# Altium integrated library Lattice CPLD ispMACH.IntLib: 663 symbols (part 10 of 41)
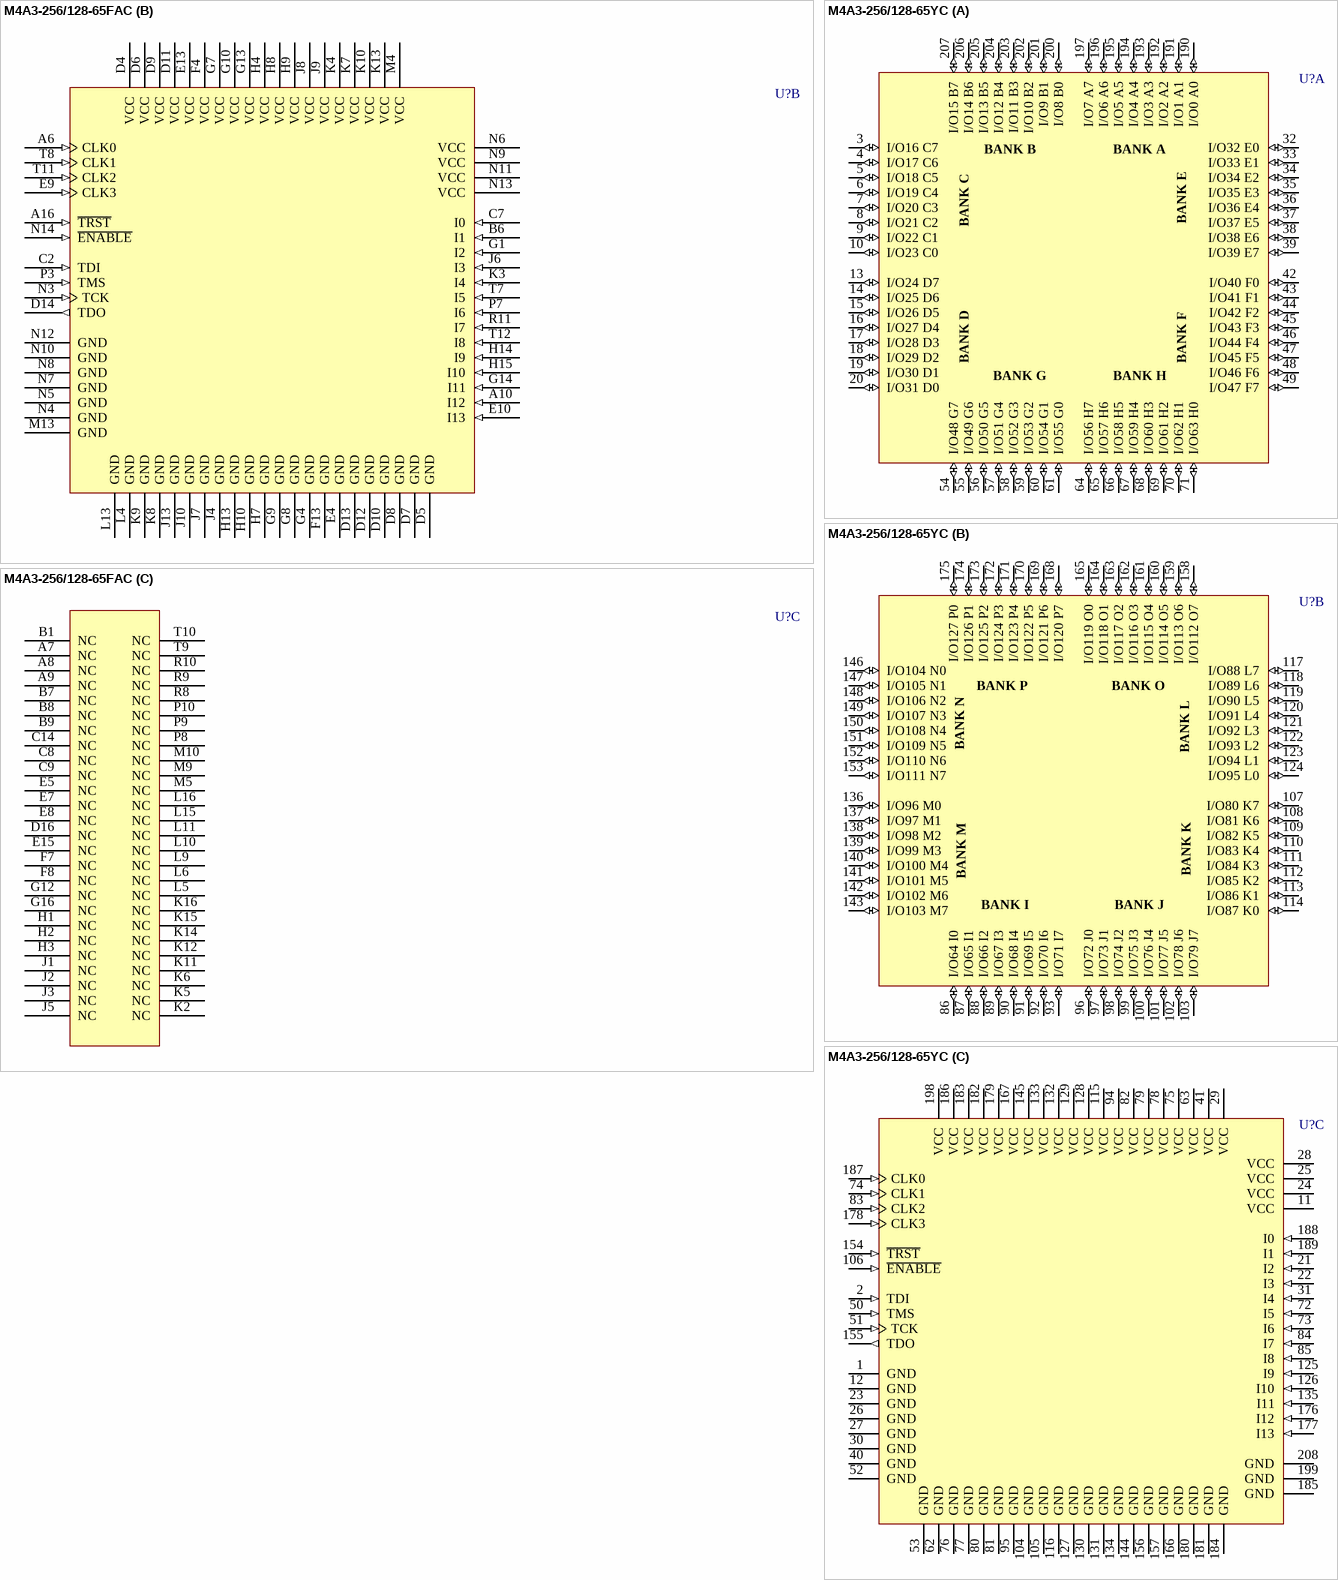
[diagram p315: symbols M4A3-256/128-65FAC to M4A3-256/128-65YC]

## M4A3-256/128-65YC
designator U?
High-Performance EE CMOS In-System Programmable Logic
footprint PQFP208_N (Shrink QFP, 208-Leads, Body 28x28mm, Pitch 0.5mm, IPC Medium Density)
footprint PQFP208_L (Shrink QFP, 208-Leads, Body 28x28mm, Pitch 0.5mm, IPC High Density)
footprint PQFP208_M (Shrink QFP, 208-Leads, Body 28x28mm, Pitch 0.5mm, IPC Low Density)
3D model M4A3-PQFP208 (208-Pin Plastic Quad Flat Pack (PQFP208))
part A pins: 3 I/O16 C7 (io), 4 I/O17 C6 (io), 5 I/O18 C5 (io), 6 I/O19 C4 (io), 7 I/O20 C3 (io), 8 I/O21 C2 (io), 9 I/O22 C1 (io), 10 I/O23 C0 (io), 13 I/O24 D7 (io), 14 I/O25 D6 (io), 15 I/O26 D5 (io), 16 I/O27 D4 (io), 17 I/O28 D3 (io), 18 I/O29 D2 (io), 19 I/O30 D1 (io), 20 I/O31 D0 (io), 32 I/O32 E0 (io), 33 I/O33 E1 (io), 34 I/O34 E2 (io), 35 I/O35 E3 (io), 36 I/O36 E4 (io), 37 I/O37 E5 (io), 38 I/O38 E6 (io), 39 I/O39 E7 (io), 42 I/O40 F0 (io), 43 I/O41 F1 (io), 44 I/O42 F2 (io), 45 I/O43 F3 (io), 46 I/O44 F4 (io), 47 I/O45 F5 (io), 48 I/O46 F6 (io), 49 I/O47 F7 (io), 54 I/O48 G7 (io), 55 I/O49 G6 (io), 56 I/O50 G5 (io), 57 I/O51 G4 (io), 58 I/O52 G3 (io), 59 I/O53 G2 (io), 60 I/O54 G1 (io), 61 I/O55 G0 (io), 64 I/O56 H7 (io), 65 I/O57 H6 (io), 66 I/O58 H5 (io), 67 I/O59 H4 (io), 68 I/O60 H3 (io), 69 I/O61 H2 (io), 70 I/O62 H1 (io), 71 I/O63 H0 (io), 190 I/O0 A0 (io), 191 I/O1 A1 (io), 192 I/O2 A2 (io), 193 I/O3 A3 (io), 194 I/O4 A4 (io), 195 I/O5 A5 (io), 196 I/O6 A6 (io), 197 I/O7 A7 (io), 200 I/O8 B0 (io), 201 I/O9 B1 (io), 202 I/O10 B2 (io), 203 I/O11 B3 (io), 204 I/O12 B4 (io), 205 I/O13 B5 (io), 206 I/O14 B6 (io), 207 I/O15 B7 (io)
part B pins: 86 I/O64 I0 (io), 87 I/O65 I1 (io), 88 I/O66 I2 (io), 89 I/O67 I3 (io), 90 I/O68 I4 (io), 91 I/O69 I5 (io), 92 I/O70 I6 (io), 93 I/O71 I7 (io), 96 I/O72 J0 (io), 97 I/O73 J1 (io), 98 I/O74 J2 (io), 99 I/O75 J3 (io), 100 I/O76 J4 (io), 101 I/O77 J5 (io), 102 I/O78 J6 (io), 103 I/O79 J7 (io), 107 I/O80 K7 (io), 108 I/O81 K6 (io), 109 I/O82 K5 (io), 110 I/O83 K4 (io), 111 I/O84 K3 (io), 112 I/O85 K2 (io), 113 I/O86 K1 (io), 114 I/O87 K0 (io), 117 I/O88 L7 (io), 118 I/O89 L6 (io), 119 I/O90 L5 (io), 120 I/O91 L4 (io), 121 I/O92 L3 (io), 122 I/O93 L2 (io), 123 I/O94 L1 (io), 124 I/O95 L0 (io), 136 I/O96 M0 (io), 137 I/O97 M1 (io), 138 I/O98 M2 (io), 139 I/O99 M3 (io), 140 I/O100 M4 (io), 141 I/O101 M5 (io), 142 I/O102 M6 (io), 143 I/O103 M7 (io), 146 I/O104 N0 (io), 147 I/O105 N1 (io), 148 I/O106 N2 (io), 149 I/O107 N3 (io), 150 I/O108 N4 (io), 151 I/O109 N5 (io), 152 I/O110 N6 (io), 153 I/O111 N7 (io), 158 I/O112 O7 (io), 159 I/O113 O6 (io), 160 I/O114 O5 (io), 161 I/O115 O4 (io), 162 I/O116 O3 (io), 163 I/O117 O2 (io), 164 I/O118 O1 (io), 165 I/O119 O0 (io), 168 I/O120 P7 (io), 169 I/O121 P6 (io), 170 I/O122 P5 (io), 171 I/O123 P4 (io), 172 I/O124 P3 (io), 173 I/O125 P2 (io), 174 I/O126 P1 (io), 175 I/O127 P0 (io)
part C pins: 1 GND (power), 2 TDI (in), 11 VCC (power), 12 GND (power), 21 I2 (in), 22 I3 (in), 23 GND (power), 24 VCC (power), 25 VCC (power), 26 GND (power), 27 GND (power), 28 VCC (power), 29 VCC (power), 30 GND (power), 31 I4 (in), 40 GND (power), 41 VCC (power), 50 TMS (in), 51 TCK (in), 52 GND (power), 53 GND (power), 62 GND (power), 63 VCC (power), 72 I5 (in), 73 I6 (in), 74 CLK1 (in), 75 VCC (power), 76 GND (power), 77 GND (power), 78 VCC (power), 79 VCC (power), 80 GND (power), 81 GND (power), 82 VCC (power), 83 CLK2 (in), 84 I7 (in), 85 I8 (in), 94 VCC (power), 95 GND (power), 104 GND (power), 105 GND (power), 106 ~{ENABLE} (in), 115 VCC (power), 116 GND (power), 125 I9 (in), 126 I10 (in), 127 GND (power), 128 VCC (power), 129 VCC (power), 130 GND (power), 131 GND (power), 132 VCC (power), 133 VCC (power), 134 GND (power), 135 I11 (in), 144 GND (power), 145 VCC (power), 154 ~{TRST} (in), 155 TDO (out), 156 GND (power), 157 GND (power), 166 GND (power), 167 VCC (power), 176 I12 (in), 177 I13 (in), 178 CLK3 (in), 179 VCC (power), 180 GND (power), 181 GND (power), 182 VCC (power), 183 VCC (power), 184 GND (power), 185 GND (power), 186 VCC (power), 187 CLK0 (in), 188 I0 (in), 189 I1 (in), 198 VCC (power), 199 GND (power), 208 GND (power)

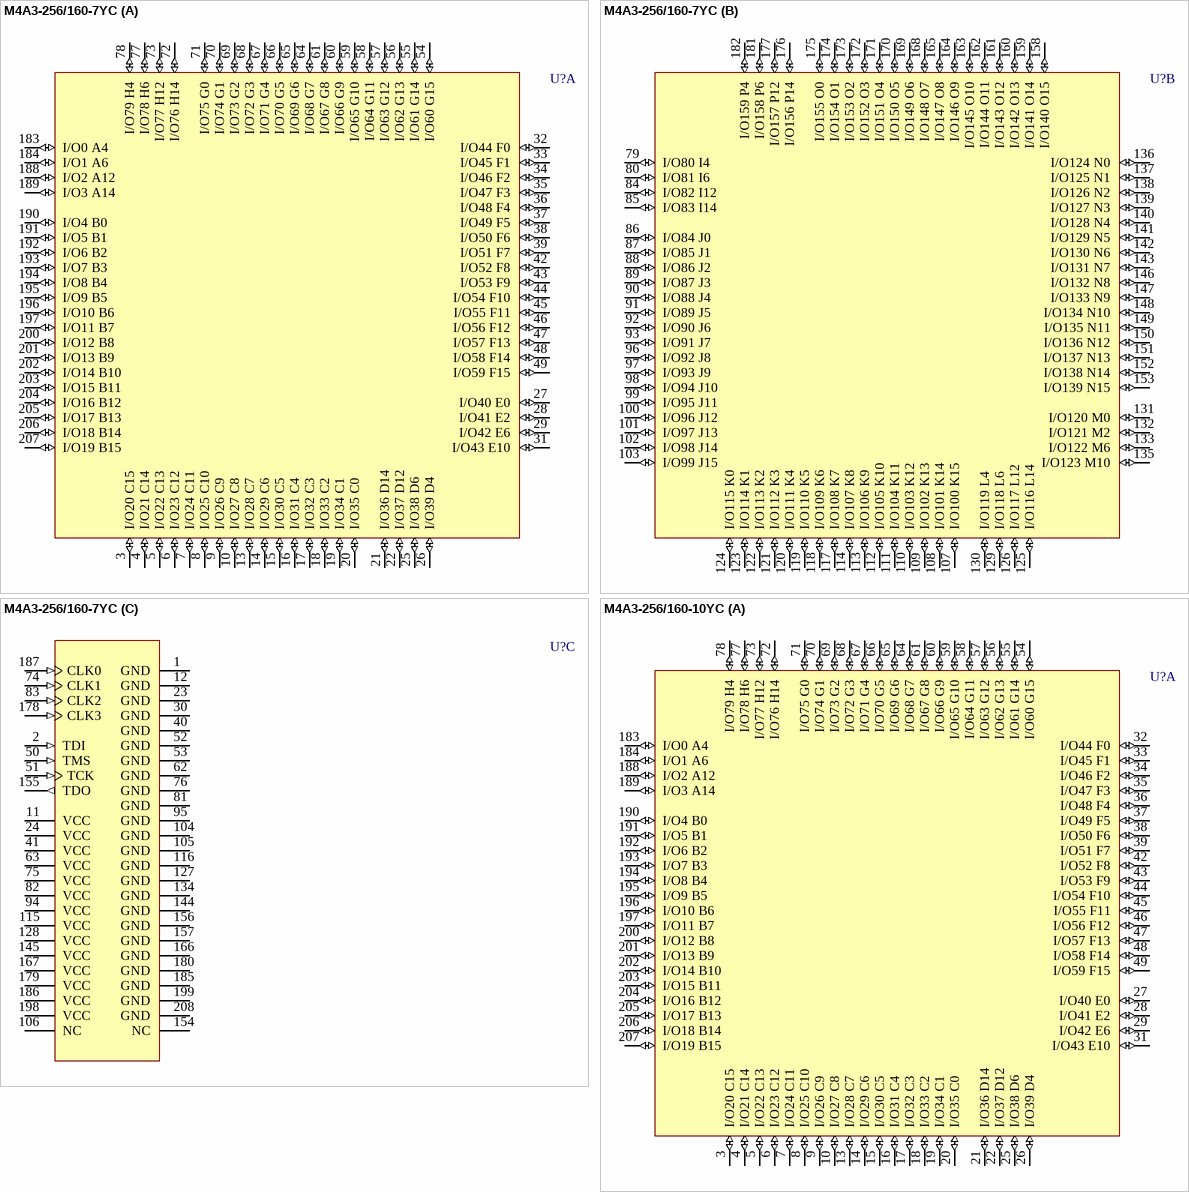
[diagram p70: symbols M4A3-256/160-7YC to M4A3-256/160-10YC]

## M4A3-256/160-7YC
designator U?
High-Performance EE CMOS In-System Programmable Logic
footprint PQFP208_N (Shrink QFP, 208-Leads, Body 28x28mm, Pitch 0.5mm, IPC Medium Density)
footprint PQFP208_L (Shrink QFP, 208-Leads, Body 28x28mm, Pitch 0.5mm, IPC High Density)
footprint PQFP208_M (Shrink QFP, 208-Leads, Body 28x28mm, Pitch 0.5mm, IPC Low Density)
3D model M4A3-PQFP208 (208-Pin Plastic Quad Flat Pack (PQFP208))
part A pins: 3 I/O20 C15 (io), 4 I/O21 C14 (io), 5 I/O22 C13 (io), 6 I/O23 C12 (io), 7 I/O24 C11 (io), 8 I/O25 C10 (io), 9 I/O26 C9 (io), 10 I/O27 C8 (io), 13 I/O28 C7 (io), 14 I/O29 C6 (io), 15 I/O30 C5 (io), 16 I/O31 C4 (io), 17 I/O32 C3 (io), 18 I/O33 C2 (io), 19 I/O34 C1 (io), 20 I/O35 C0 (io), 21 I/O36 D14 (io), 22 I/O37 D12 (io), 25 I/O38 D6 (io), 26 I/O39 D4 (io), 27 I/O40 E0 (io), 28 I/O41 E2 (io), 29 I/O42 E6 (io), 31 I/O43 E10 (io), 32 I/O44 F0 (io), 33 I/O45 F1 (io), 34 I/O46 F2 (io), 35 I/O47 F3 (io), 36 I/O48 F4 (io), 37 I/O49 F5 (io), 38 I/O50 F6 (io), 39 I/O51 F7 (io), 42 I/O52 F8 (io), 43 I/O53 F9 (io), 44 I/O54 F10 (io), 45 I/O55 F11 (io), 46 I/O56 F12 (io), 47 I/O57 F13 (io), 48 I/O58 F14 (io), 49 I/O59 F15 (io), 54 I/O60 G15 (io), 55 I/O61 G14 (io), 56 I/O62 G13 (io), 57 I/O63 G12 (io), 58 I/O64 G11 (io), 59 I/O65 G10 (io), 60 I/O66 G9 (io), 61 I/O67 G8 (io), 64 I/O68 G7 (io), 65 I/O69 G6 (io), 66 I/O70 G5 (io), 67 I/O71 G4 (io), 68 I/O72 G3 (io), 69 I/O73 G2 (io), 70 I/O74 G1 (io), 71 I/O75 G0 (io), 72 I/O76 H14 (io), 73 I/O77 H12 (io), 77 I/O78 H6 (io), 78 I/O79 H4 (io), 183 I/O0 A4 (io), 184 I/O1 A6 (io), 188 I/O2 A12 (io), 189 I/O3 A14 (io), 190 I/O4 B0 (io), 191 I/O5 B1 (io), 192 I/O6 B2 (io), 193 I/O7 B3 (io), 194 I/O8 B4 (io), 195 I/O9 B5 (io), 196 I/O10 B6 (io), 197 I/O11 B7 (io), 200 I/O12 B8 (io), 201 I/O13 B9 (io), 202 I/O14 B10 (io), 203 I/O15 B11 (io), 204 I/O16 B12 (io), 205 I/O17 B13 (io), 206 I/O18 B14 (io), 207 I/O19 B15 (io)
part B pins: 79 I/O80 I4 (io), 80 I/O81 I6 (io), 84 I/O82 I12 (io), 85 I/O83 I14 (io), 86 I/O84 J0 (io), 87 I/O85 J1 (io), 88 I/O86 J2 (io), 89 I/O87 J3 (io), 90 I/O88 J4 (io), 91 I/O89 J5 (io), 92 I/O90 J6 (io), 93 I/O91 J7 (io), 96 I/O92 J8 (io), 97 I/O93 J9 (io), 98 I/O94 J10 (io), 99 I/O95 J11 (io), 100 I/O96 J12 (io), 101 I/O97 J13 (io), 102 I/O98 J14 (io), 103 I/O99 J15 (io), 107 I/O100 K15 (io), 108 I/O101 K14 (io), 109 I/O102 K13 (io), 110 I/O103 K12 (io), 111 I/O104 K11 (io), 112 I/O105 K10 (io), 113 I/O106 K9 (io), 114 I/O107 K8 (io), 117 I/O108 K7 (io), 118 I/O109 K6 (io), 119 I/O110 K5 (io), 120 I/O111 K4 (io), 121 I/O112 K3 (io), 122 I/O113 K2 (io), 123 I/O114 K1 (io), 124 I/O115 K0 (io), 125 I/O116 L14 (io), 126 I/O117 L12 (io), 129 I/O118 L6 (io), 130 I/O119 L4 (io), 131 I/O120 M0 (io), 132 I/O121 M2 (io), 133 I/O122 M6 (io), 135 I/O123 M10 (io), 136 I/O124 N0 (io), 137 I/O125 N1 (io), 138 I/O126 N2 (io), 139 I/O127 N3 (io), 140 I/O128 N4 (io), 141 I/O129 N5 (io), 142 I/O130 N6 (io), 143 I/O131 N7 (io), 146 I/O132 N8 (io), 147 I/O133 N9 (io), 148 I/O134 N10 (io), 149 I/O135 N11 (io), 150 I/O136 N12 (io), 151 I/O137 N13 (io), 152 I/O138 N14 (io), 153 I/O139 N15 (io), 158 I/O140 O15 (io), 159 I/O141 O14 (io), 160 I/O142 O13 (io), 161 I/O143 O12 (io), 162 I/O144 O11 (io), 163 I/O145 O10 (io), 164 I/O146 O9 (io), 165 I/O147 O8 (io), 168 I/O148 O7 (io), 169 I/O149 O6 (io), 170 I/O150 O5 (io), 171 I/O151 O4 (io), 172 I/O152 O3 (io), 173 I/O153 O2 (io), 174 I/O154 O1 (io), 175 I/O155 O0 (io), 176 I/O156 P14 (io), 177 I/O157 P12 (io), 181 I/O158 P6 (io), 182 I/O159 P4 (io)
part C pins: 1 GND (power), 2 TDI (in), 11 VCC (power), 12 GND (power), 23 GND (power), 24 VCC (power), 30 GND (power), 40 GND (power), 41 VCC (power), 50 TMS (in), 51 TCK (in), 52 GND (power), 53 GND (power), 62 GND (power), 63 VCC (power), 74 CLK1 (in), 75 VCC (power), 76 GND (power), 81 GND (power), 82 VCC (power), 83 CLK2 (in), 94 VCC (power), 95 GND (power), 104 GND (power), 105 GND (power), 106 NC, 115 VCC (power), 116 GND (power), 127 GND (power), 128 VCC (power), 134 GND (power), 144 GND (power), 145 VCC (power), 154 NC, 155 TDO (out), 156 GND (power), 157 GND (power), 166 GND (power), 167 VCC (power), 178 CLK3 (in), 179 VCC (power), 180 GND (power), 185 GND (power), 186 VCC (power), 187 CLK0 (in), 198 VCC (power), 199 GND (power), 208 GND (power)

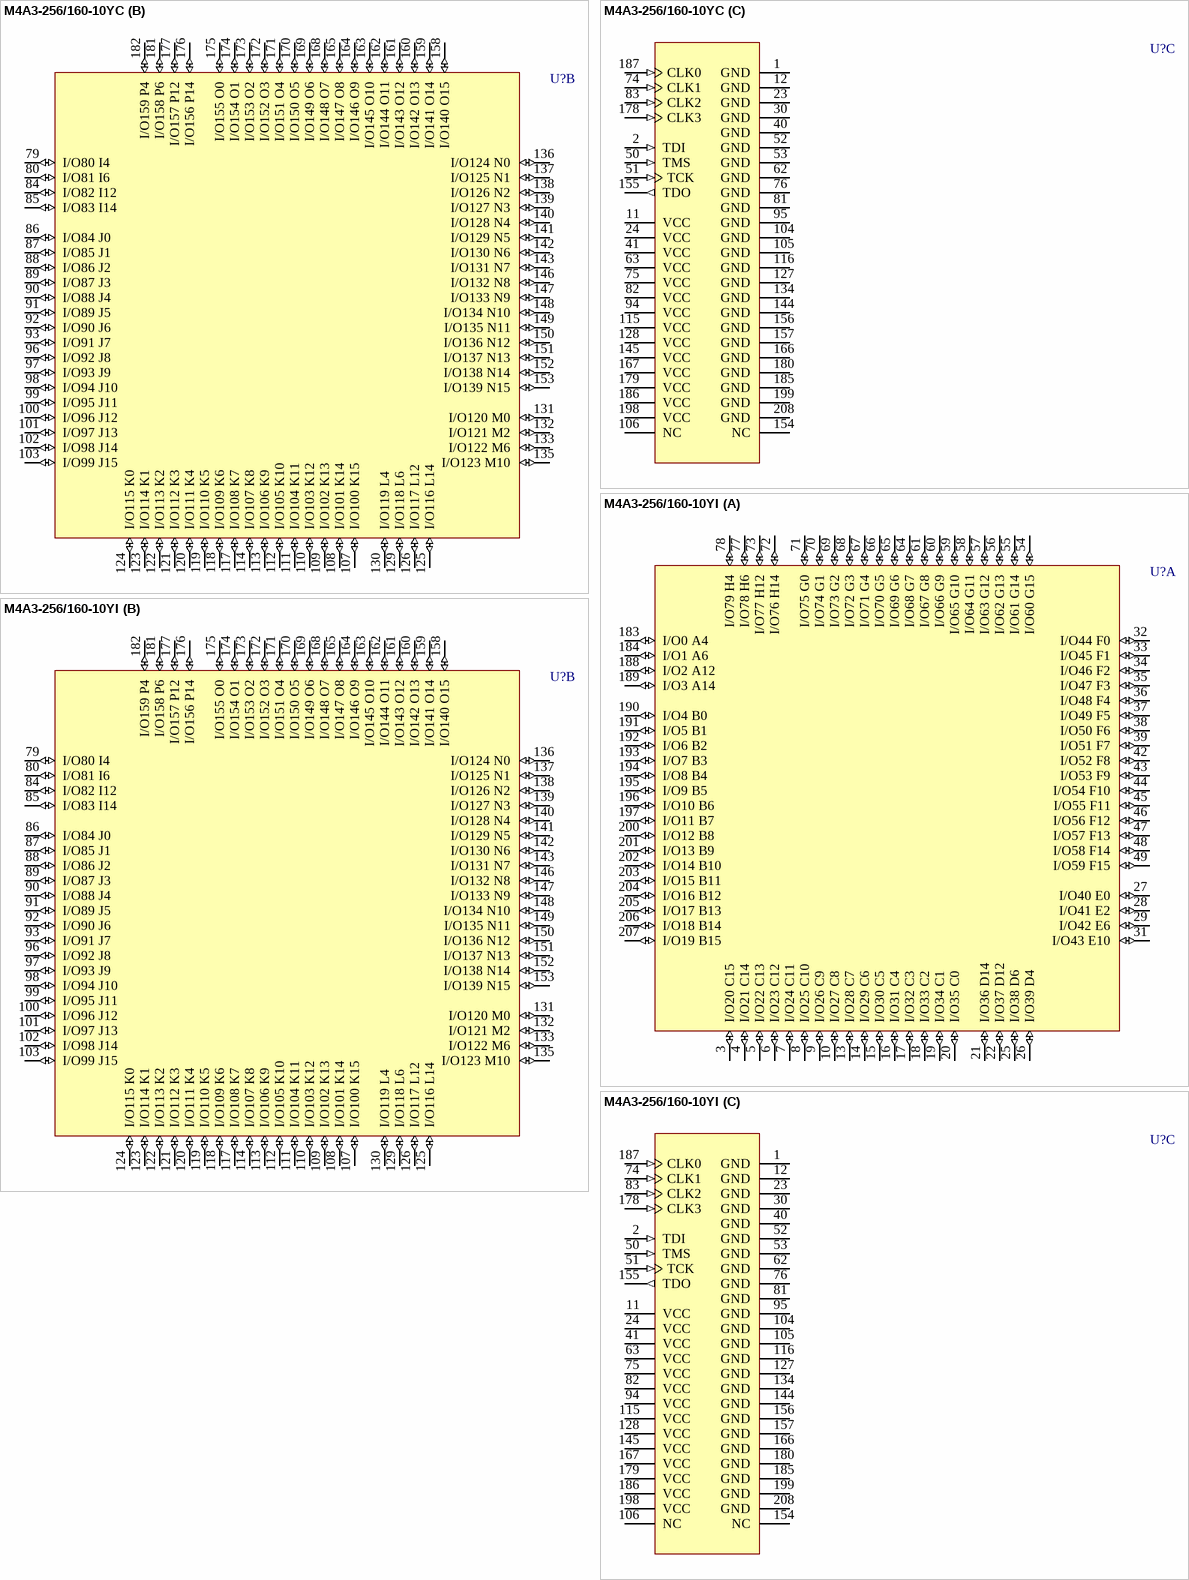
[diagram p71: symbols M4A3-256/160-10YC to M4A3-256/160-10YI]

## M4A3-256/160-10YC
designator U?
High-Performance EE CMOS In-System Programmable Logic
footprint PQFP208_N (Shrink QFP, 208-Leads, Body 28x28mm, Pitch 0.5mm, IPC Medium Density)
footprint PQFP208_L (Shrink QFP, 208-Leads, Body 28x28mm, Pitch 0.5mm, IPC High Density)
footprint PQFP208_M (Shrink QFP, 208-Leads, Body 28x28mm, Pitch 0.5mm, IPC Low Density)
3D model M4A3-PQFP208 (208-Pin Plastic Quad Flat Pack (PQFP208))
part A pins: 3 I/O20 C15 (io), 4 I/O21 C14 (io), 5 I/O22 C13 (io), 6 I/O23 C12 (io), 7 I/O24 C11 (io), 8 I/O25 C10 (io), 9 I/O26 C9 (io), 10 I/O27 C8 (io), 13 I/O28 C7 (io), 14 I/O29 C6 (io), 15 I/O30 C5 (io), 16 I/O31 C4 (io), 17 I/O32 C3 (io), 18 I/O33 C2 (io), 19 I/O34 C1 (io), 20 I/O35 C0 (io), 21 I/O36 D14 (io), 22 I/O37 D12 (io), 25 I/O38 D6 (io), 26 I/O39 D4 (io), 27 I/O40 E0 (io), 28 I/O41 E2 (io), 29 I/O42 E6 (io), 31 I/O43 E10 (io), 32 I/O44 F0 (io), 33 I/O45 F1 (io), 34 I/O46 F2 (io), 35 I/O47 F3 (io), 36 I/O48 F4 (io), 37 I/O49 F5 (io), 38 I/O50 F6 (io), 39 I/O51 F7 (io), 42 I/O52 F8 (io), 43 I/O53 F9 (io), 44 I/O54 F10 (io), 45 I/O55 F11 (io), 46 I/O56 F12 (io), 47 I/O57 F13 (io), 48 I/O58 F14 (io), 49 I/O59 F15 (io), 54 I/O60 G15 (io), 55 I/O61 G14 (io), 56 I/O62 G13 (io), 57 I/O63 G12 (io), 58 I/O64 G11 (io), 59 I/O65 G10 (io), 60 I/O66 G9 (io), 61 I/O67 G8 (io), 64 I/O68 G7 (io), 65 I/O69 G6 (io), 66 I/O70 G5 (io), 67 I/O71 G4 (io), 68 I/O72 G3 (io), 69 I/O73 G2 (io), 70 I/O74 G1 (io), 71 I/O75 G0 (io), 72 I/O76 H14 (io), 73 I/O77 H12 (io), 77 I/O78 H6 (io), 78 I/O79 H4 (io), 183 I/O0 A4 (io), 184 I/O1 A6 (io), 188 I/O2 A12 (io), 189 I/O3 A14 (io), 190 I/O4 B0 (io), 191 I/O5 B1 (io), 192 I/O6 B2 (io), 193 I/O7 B3 (io), 194 I/O8 B4 (io), 195 I/O9 B5 (io), 196 I/O10 B6 (io), 197 I/O11 B7 (io), 200 I/O12 B8 (io), 201 I/O13 B9 (io), 202 I/O14 B10 (io), 203 I/O15 B11 (io), 204 I/O16 B12 (io), 205 I/O17 B13 (io), 206 I/O18 B14 (io), 207 I/O19 B15 (io)
part B pins: 79 I/O80 I4 (io), 80 I/O81 I6 (io), 84 I/O82 I12 (io), 85 I/O83 I14 (io), 86 I/O84 J0 (io), 87 I/O85 J1 (io), 88 I/O86 J2 (io), 89 I/O87 J3 (io), 90 I/O88 J4 (io), 91 I/O89 J5 (io), 92 I/O90 J6 (io), 93 I/O91 J7 (io), 96 I/O92 J8 (io), 97 I/O93 J9 (io), 98 I/O94 J10 (io), 99 I/O95 J11 (io), 100 I/O96 J12 (io), 101 I/O97 J13 (io), 102 I/O98 J14 (io), 103 I/O99 J15 (io), 107 I/O100 K15 (io), 108 I/O101 K14 (io), 109 I/O102 K13 (io), 110 I/O103 K12 (io), 111 I/O104 K11 (io), 112 I/O105 K10 (io), 113 I/O106 K9 (io), 114 I/O107 K8 (io), 117 I/O108 K7 (io), 118 I/O109 K6 (io), 119 I/O110 K5 (io), 120 I/O111 K4 (io), 121 I/O112 K3 (io), 122 I/O113 K2 (io), 123 I/O114 K1 (io), 124 I/O115 K0 (io), 125 I/O116 L14 (io), 126 I/O117 L12 (io), 129 I/O118 L6 (io), 130 I/O119 L4 (io), 131 I/O120 M0 (io), 132 I/O121 M2 (io), 133 I/O122 M6 (io), 135 I/O123 M10 (io), 136 I/O124 N0 (io), 137 I/O125 N1 (io), 138 I/O126 N2 (io), 139 I/O127 N3 (io), 140 I/O128 N4 (io), 141 I/O129 N5 (io), 142 I/O130 N6 (io), 143 I/O131 N7 (io), 146 I/O132 N8 (io), 147 I/O133 N9 (io), 148 I/O134 N10 (io), 149 I/O135 N11 (io), 150 I/O136 N12 (io), 151 I/O137 N13 (io), 152 I/O138 N14 (io), 153 I/O139 N15 (io), 158 I/O140 O15 (io), 159 I/O141 O14 (io), 160 I/O142 O13 (io), 161 I/O143 O12 (io), 162 I/O144 O11 (io), 163 I/O145 O10 (io), 164 I/O146 O9 (io), 165 I/O147 O8 (io), 168 I/O148 O7 (io), 169 I/O149 O6 (io), 170 I/O150 O5 (io), 171 I/O151 O4 (io), 172 I/O152 O3 (io), 173 I/O153 O2 (io), 174 I/O154 O1 (io), 175 I/O155 O0 (io), 176 I/O156 P14 (io), 177 I/O157 P12 (io), 181 I/O158 P6 (io), 182 I/O159 P4 (io)
part C pins: 1 GND (power), 2 TDI (in), 11 VCC (power), 12 GND (power), 23 GND (power), 24 VCC (power), 30 GND (power), 40 GND (power), 41 VCC (power), 50 TMS (in), 51 TCK (in), 52 GND (power), 53 GND (power), 62 GND (power), 63 VCC (power), 74 CLK1 (in), 75 VCC (power), 76 GND (power), 81 GND (power), 82 VCC (power), 83 CLK2 (in), 94 VCC (power), 95 GND (power), 104 GND (power), 105 GND (power), 106 NC, 115 VCC (power), 116 GND (power), 127 GND (power), 128 VCC (power), 134 GND (power), 144 GND (power), 145 VCC (power), 154 NC, 155 TDO (out), 156 GND (power), 157 GND (power), 166 GND (power), 167 VCC (power), 178 CLK3 (in), 179 VCC (power), 180 GND (power), 185 GND (power), 186 VCC (power), 187 CLK0 (in), 198 VCC (power), 199 GND (power), 208 GND (power)

## M4A3-256/160-10YI
designator U?
High-Performance EE CMOS In-System Programmable Logic
footprint PQFP208_N (Shrink QFP, 208-Leads, Body 28x28mm, Pitch 0.5mm, IPC Medium Density)
footprint PQFP208_L (Shrink QFP, 208-Leads, Body 28x28mm, Pitch 0.5mm, IPC High Density)
footprint PQFP208_M (Shrink QFP, 208-Leads, Body 28x28mm, Pitch 0.5mm, IPC Low Density)
3D model M4A3-PQFP208 (208-Pin Plastic Quad Flat Pack (PQFP208))
part A pins: 3 I/O20 C15 (io), 4 I/O21 C14 (io), 5 I/O22 C13 (io), 6 I/O23 C12 (io), 7 I/O24 C11 (io), 8 I/O25 C10 (io), 9 I/O26 C9 (io), 10 I/O27 C8 (io), 13 I/O28 C7 (io), 14 I/O29 C6 (io), 15 I/O30 C5 (io), 16 I/O31 C4 (io), 17 I/O32 C3 (io), 18 I/O33 C2 (io), 19 I/O34 C1 (io), 20 I/O35 C0 (io), 21 I/O36 D14 (io), 22 I/O37 D12 (io), 25 I/O38 D6 (io), 26 I/O39 D4 (io), 27 I/O40 E0 (io), 28 I/O41 E2 (io), 29 I/O42 E6 (io), 31 I/O43 E10 (io), 32 I/O44 F0 (io), 33 I/O45 F1 (io), 34 I/O46 F2 (io), 35 I/O47 F3 (io), 36 I/O48 F4 (io), 37 I/O49 F5 (io), 38 I/O50 F6 (io), 39 I/O51 F7 (io), 42 I/O52 F8 (io), 43 I/O53 F9 (io), 44 I/O54 F10 (io), 45 I/O55 F11 (io), 46 I/O56 F12 (io), 47 I/O57 F13 (io), 48 I/O58 F14 (io), 49 I/O59 F15 (io), 54 I/O60 G15 (io), 55 I/O61 G14 (io), 56 I/O62 G13 (io), 57 I/O63 G12 (io), 58 I/O64 G11 (io), 59 I/O65 G10 (io), 60 I/O66 G9 (io), 61 I/O67 G8 (io), 64 I/O68 G7 (io), 65 I/O69 G6 (io), 66 I/O70 G5 (io), 67 I/O71 G4 (io), 68 I/O72 G3 (io), 69 I/O73 G2 (io), 70 I/O74 G1 (io), 71 I/O75 G0 (io), 72 I/O76 H14 (io), 73 I/O77 H12 (io), 77 I/O78 H6 (io), 78 I/O79 H4 (io), 183 I/O0 A4 (io), 184 I/O1 A6 (io), 188 I/O2 A12 (io), 189 I/O3 A14 (io), 190 I/O4 B0 (io), 191 I/O5 B1 (io), 192 I/O6 B2 (io), 193 I/O7 B3 (io), 194 I/O8 B4 (io), 195 I/O9 B5 (io), 196 I/O10 B6 (io), 197 I/O11 B7 (io), 200 I/O12 B8 (io), 201 I/O13 B9 (io), 202 I/O14 B10 (io), 203 I/O15 B11 (io), 204 I/O16 B12 (io), 205 I/O17 B13 (io), 206 I/O18 B14 (io), 207 I/O19 B15 (io)
part B pins: 79 I/O80 I4 (io), 80 I/O81 I6 (io), 84 I/O82 I12 (io), 85 I/O83 I14 (io), 86 I/O84 J0 (io), 87 I/O85 J1 (io), 88 I/O86 J2 (io), 89 I/O87 J3 (io), 90 I/O88 J4 (io), 91 I/O89 J5 (io), 92 I/O90 J6 (io), 93 I/O91 J7 (io), 96 I/O92 J8 (io), 97 I/O93 J9 (io), 98 I/O94 J10 (io), 99 I/O95 J11 (io), 100 I/O96 J12 (io), 101 I/O97 J13 (io), 102 I/O98 J14 (io), 103 I/O99 J15 (io), 107 I/O100 K15 (io), 108 I/O101 K14 (io), 109 I/O102 K13 (io), 110 I/O103 K12 (io), 111 I/O104 K11 (io), 112 I/O105 K10 (io), 113 I/O106 K9 (io), 114 I/O107 K8 (io), 117 I/O108 K7 (io), 118 I/O109 K6 (io), 119 I/O110 K5 (io), 120 I/O111 K4 (io), 121 I/O112 K3 (io), 122 I/O113 K2 (io), 123 I/O114 K1 (io), 124 I/O115 K0 (io), 125 I/O116 L14 (io), 126 I/O117 L12 (io), 129 I/O118 L6 (io), 130 I/O119 L4 (io), 131 I/O120 M0 (io), 132 I/O121 M2 (io), 133 I/O122 M6 (io), 135 I/O123 M10 (io), 136 I/O124 N0 (io), 137 I/O125 N1 (io), 138 I/O126 N2 (io), 139 I/O127 N3 (io), 140 I/O128 N4 (io), 141 I/O129 N5 (io), 142 I/O130 N6 (io), 143 I/O131 N7 (io), 146 I/O132 N8 (io), 147 I/O133 N9 (io), 148 I/O134 N10 (io), 149 I/O135 N11 (io), 150 I/O136 N12 (io), 151 I/O137 N13 (io), 152 I/O138 N14 (io), 153 I/O139 N15 (io), 158 I/O140 O15 (io), 159 I/O141 O14 (io), 160 I/O142 O13 (io), 161 I/O143 O12 (io), 162 I/O144 O11 (io), 163 I/O145 O10 (io), 164 I/O146 O9 (io), 165 I/O147 O8 (io), 168 I/O148 O7 (io), 169 I/O149 O6 (io), 170 I/O150 O5 (io), 171 I/O151 O4 (io), 172 I/O152 O3 (io), 173 I/O153 O2 (io), 174 I/O154 O1 (io), 175 I/O155 O0 (io), 176 I/O156 P14 (io), 177 I/O157 P12 (io), 181 I/O158 P6 (io), 182 I/O159 P4 (io)
part C pins: 1 GND (power), 2 TDI (in), 11 VCC (power), 12 GND (power), 23 GND (power), 24 VCC (power), 30 GND (power), 40 GND (power), 41 VCC (power), 50 TMS (in), 51 TCK (in), 52 GND (power), 53 GND (power), 62 GND (power), 63 VCC (power), 74 CLK1 (in), 75 VCC (power), 76 GND (power), 81 GND (power), 82 VCC (power), 83 CLK2 (in), 94 VCC (power), 95 GND (power), 104 GND (power), 105 GND (power), 106 NC, 115 VCC (power), 116 GND (power), 127 GND (power), 128 VCC (power), 134 GND (power), 144 GND (power), 145 VCC (power), 154 NC, 155 TDO (out), 156 GND (power), 157 GND (power), 166 GND (power), 167 VCC (power), 178 CLK3 (in), 179 VCC (power), 180 GND (power), 185 GND (power), 186 VCC (power), 187 CLK0 (in), 198 VCC (power), 199 GND (power), 208 GND (power)

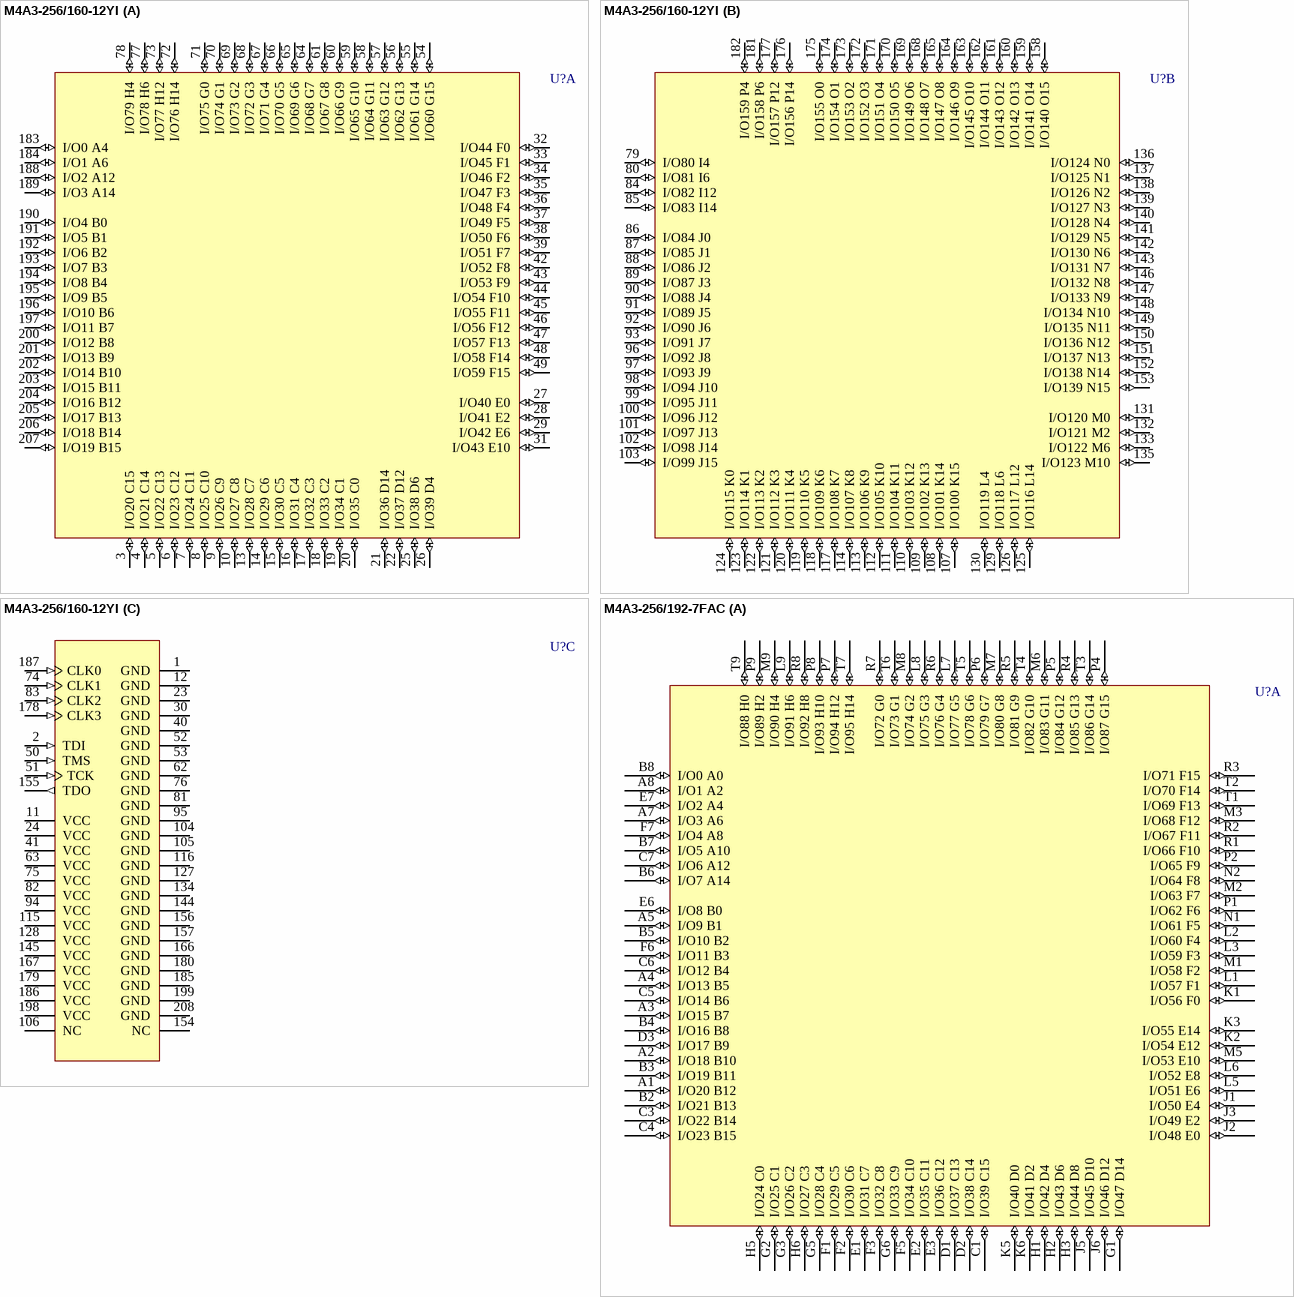
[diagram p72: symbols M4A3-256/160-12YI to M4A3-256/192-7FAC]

## M4A3-256/160-12YI
designator U?
High-Performance EE CMOS In-System Programmable Logic
footprint PQFP208_N (Shrink QFP, 208-Leads, Body 28x28mm, Pitch 0.5mm, IPC Medium Density)
footprint PQFP208_L (Shrink QFP, 208-Leads, Body 28x28mm, Pitch 0.5mm, IPC High Density)
footprint PQFP208_M (Shrink QFP, 208-Leads, Body 28x28mm, Pitch 0.5mm, IPC Low Density)
3D model M4A3-PQFP208 (208-Pin Plastic Quad Flat Pack (PQFP208))
part A pins: 3 I/O20 C15 (io), 4 I/O21 C14 (io), 5 I/O22 C13 (io), 6 I/O23 C12 (io), 7 I/O24 C11 (io), 8 I/O25 C10 (io), 9 I/O26 C9 (io), 10 I/O27 C8 (io), 13 I/O28 C7 (io), 14 I/O29 C6 (io), 15 I/O30 C5 (io), 16 I/O31 C4 (io), 17 I/O32 C3 (io), 18 I/O33 C2 (io), 19 I/O34 C1 (io), 20 I/O35 C0 (io), 21 I/O36 D14 (io), 22 I/O37 D12 (io), 25 I/O38 D6 (io), 26 I/O39 D4 (io), 27 I/O40 E0 (io), 28 I/O41 E2 (io), 29 I/O42 E6 (io), 31 I/O43 E10 (io), 32 I/O44 F0 (io), 33 I/O45 F1 (io), 34 I/O46 F2 (io), 35 I/O47 F3 (io), 36 I/O48 F4 (io), 37 I/O49 F5 (io), 38 I/O50 F6 (io), 39 I/O51 F7 (io), 42 I/O52 F8 (io), 43 I/O53 F9 (io), 44 I/O54 F10 (io), 45 I/O55 F11 (io), 46 I/O56 F12 (io), 47 I/O57 F13 (io), 48 I/O58 F14 (io), 49 I/O59 F15 (io), 54 I/O60 G15 (io), 55 I/O61 G14 (io), 56 I/O62 G13 (io), 57 I/O63 G12 (io), 58 I/O64 G11 (io), 59 I/O65 G10 (io), 60 I/O66 G9 (io), 61 I/O67 G8 (io), 64 I/O68 G7 (io), 65 I/O69 G6 (io), 66 I/O70 G5 (io), 67 I/O71 G4 (io), 68 I/O72 G3 (io), 69 I/O73 G2 (io), 70 I/O74 G1 (io), 71 I/O75 G0 (io), 72 I/O76 H14 (io), 73 I/O77 H12 (io), 77 I/O78 H6 (io), 78 I/O79 H4 (io), 183 I/O0 A4 (io), 184 I/O1 A6 (io), 188 I/O2 A12 (io), 189 I/O3 A14 (io), 190 I/O4 B0 (io), 191 I/O5 B1 (io), 192 I/O6 B2 (io), 193 I/O7 B3 (io), 194 I/O8 B4 (io), 195 I/O9 B5 (io), 196 I/O10 B6 (io), 197 I/O11 B7 (io), 200 I/O12 B8 (io), 201 I/O13 B9 (io), 202 I/O14 B10 (io), 203 I/O15 B11 (io), 204 I/O16 B12 (io), 205 I/O17 B13 (io), 206 I/O18 B14 (io), 207 I/O19 B15 (io)
part B pins: 79 I/O80 I4 (io), 80 I/O81 I6 (io), 84 I/O82 I12 (io), 85 I/O83 I14 (io), 86 I/O84 J0 (io), 87 I/O85 J1 (io), 88 I/O86 J2 (io), 89 I/O87 J3 (io), 90 I/O88 J4 (io), 91 I/O89 J5 (io), 92 I/O90 J6 (io), 93 I/O91 J7 (io), 96 I/O92 J8 (io), 97 I/O93 J9 (io), 98 I/O94 J10 (io), 99 I/O95 J11 (io), 100 I/O96 J12 (io), 101 I/O97 J13 (io), 102 I/O98 J14 (io), 103 I/O99 J15 (io), 107 I/O100 K15 (io), 108 I/O101 K14 (io), 109 I/O102 K13 (io), 110 I/O103 K12 (io), 111 I/O104 K11 (io), 112 I/O105 K10 (io), 113 I/O106 K9 (io), 114 I/O107 K8 (io), 117 I/O108 K7 (io), 118 I/O109 K6 (io), 119 I/O110 K5 (io), 120 I/O111 K4 (io), 121 I/O112 K3 (io), 122 I/O113 K2 (io), 123 I/O114 K1 (io), 124 I/O115 K0 (io), 125 I/O116 L14 (io), 126 I/O117 L12 (io), 129 I/O118 L6 (io), 130 I/O119 L4 (io), 131 I/O120 M0 (io), 132 I/O121 M2 (io), 133 I/O122 M6 (io), 135 I/O123 M10 (io), 136 I/O124 N0 (io), 137 I/O125 N1 (io), 138 I/O126 N2 (io), 139 I/O127 N3 (io), 140 I/O128 N4 (io), 141 I/O129 N5 (io), 142 I/O130 N6 (io), 143 I/O131 N7 (io), 146 I/O132 N8 (io), 147 I/O133 N9 (io), 148 I/O134 N10 (io), 149 I/O135 N11 (io), 150 I/O136 N12 (io), 151 I/O137 N13 (io), 152 I/O138 N14 (io), 153 I/O139 N15 (io), 158 I/O140 O15 (io), 159 I/O141 O14 (io), 160 I/O142 O13 (io), 161 I/O143 O12 (io), 162 I/O144 O11 (io), 163 I/O145 O10 (io), 164 I/O146 O9 (io), 165 I/O147 O8 (io), 168 I/O148 O7 (io), 169 I/O149 O6 (io), 170 I/O150 O5 (io), 171 I/O151 O4 (io), 172 I/O152 O3 (io), 173 I/O153 O2 (io), 174 I/O154 O1 (io), 175 I/O155 O0 (io), 176 I/O156 P14 (io), 177 I/O157 P12 (io), 181 I/O158 P6 (io), 182 I/O159 P4 (io)
part C pins: 1 GND (power), 2 TDI (in), 11 VCC (power), 12 GND (power), 23 GND (power), 24 VCC (power), 30 GND (power), 40 GND (power), 41 VCC (power), 50 TMS (in), 51 TCK (in), 52 GND (power), 53 GND (power), 62 GND (power), 63 VCC (power), 74 CLK1 (in), 75 VCC (power), 76 GND (power), 81 GND (power), 82 VCC (power), 83 CLK2 (in), 94 VCC (power), 95 GND (power), 104 GND (power), 105 GND (power), 106 NC, 115 VCC (power), 116 GND (power), 127 GND (power), 128 VCC (power), 134 GND (power), 144 GND (power), 145 VCC (power), 154 NC, 155 TDO (out), 156 GND (power), 157 GND (power), 166 GND (power), 167 VCC (power), 178 CLK3 (in), 179 VCC (power), 180 GND (power), 185 GND (power), 186 VCC (power), 187 CLK0 (in), 198 VCC (power), 199 GND (power), 208 GND (power)

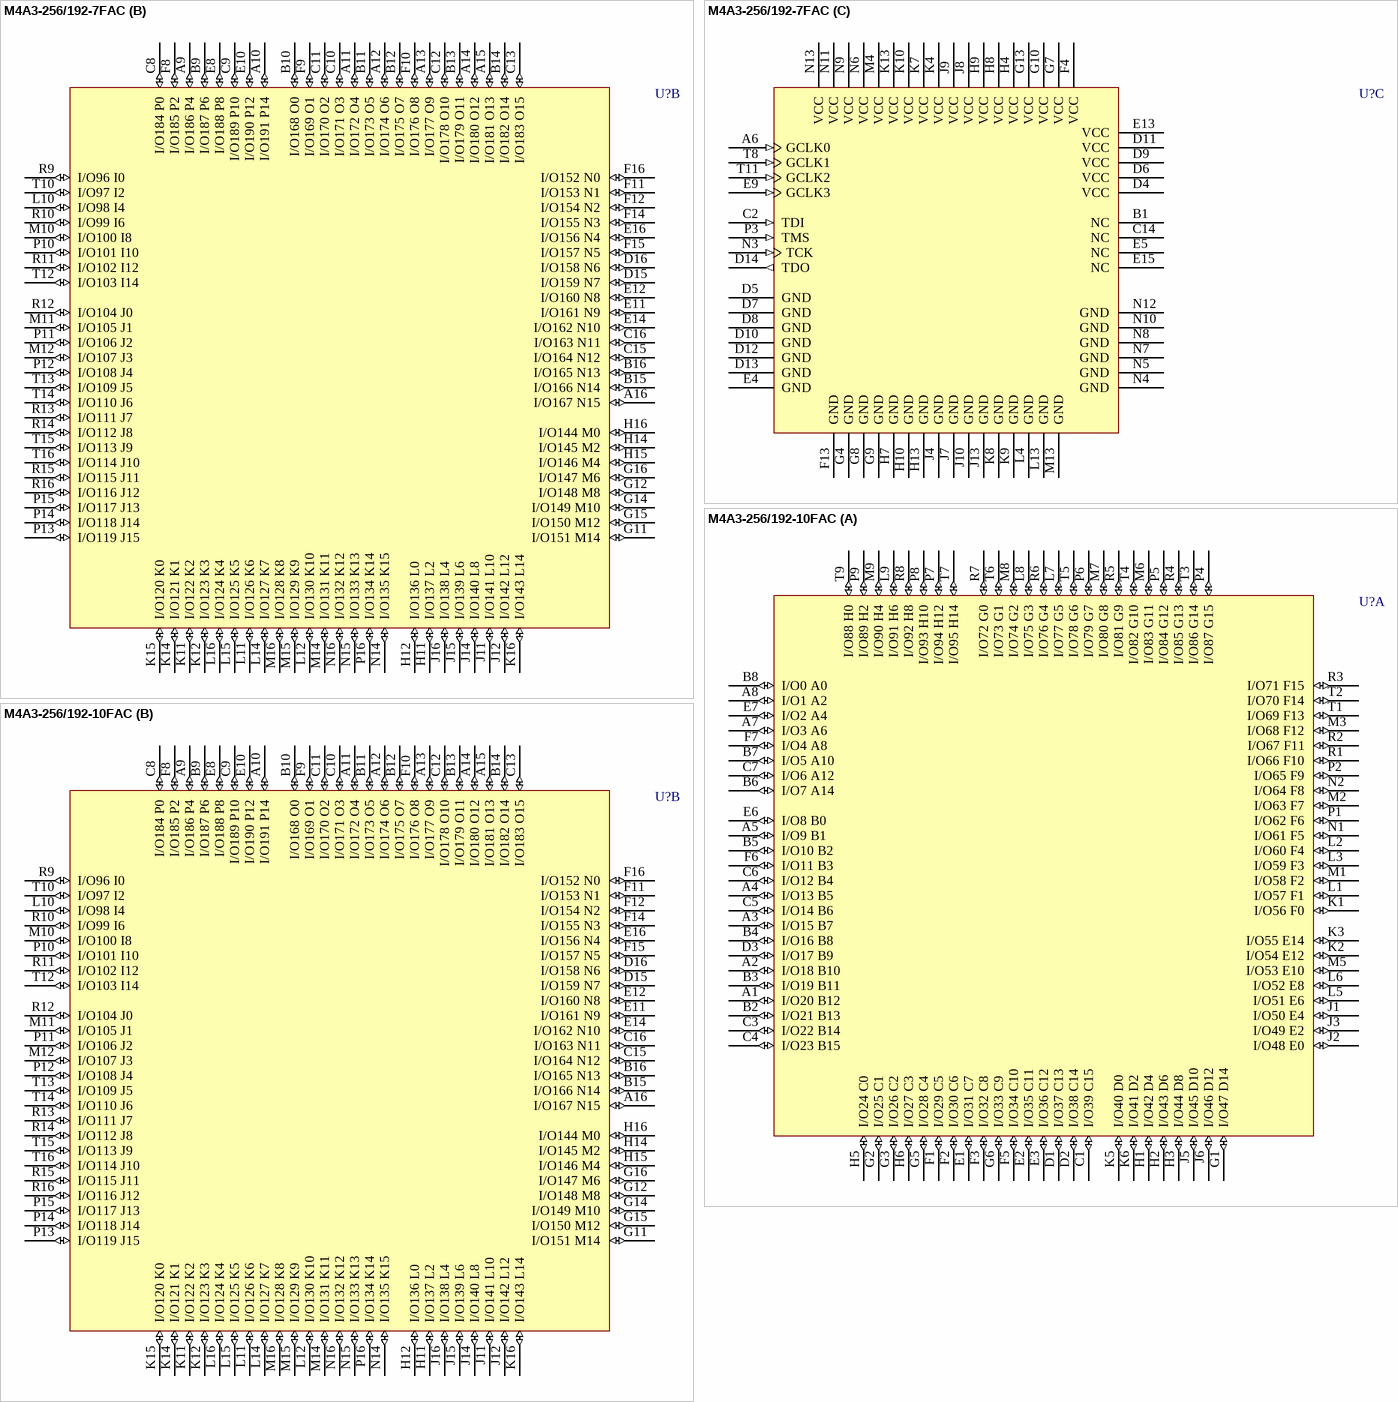
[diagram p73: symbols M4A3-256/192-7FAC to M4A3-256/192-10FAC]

## M4A3-256/192-7FAC
designator U?
High-Performance EE CMOS In-System Programmable Logic
footprint fpBGA256 (BGA, 256-Leads, Body 17x17mm, Pitch 1mm)
3D model M4A3-fpBGA256 (256-Ball Fine Pitch Ball Grid Array (fpBGA256))
part A pins: A1 I/O20 B12 (io), A2 I/O18 B10 (io), A3 I/O15 B7 (io), A4 I/O13 B5 (io), A5 I/O9 B1 (io), A7 I/O3 A6 (io), A8 I/O1 A2 (io), B2 I/O21 B13 (io), B3 I/O19 B11 (io), B4 I/O16 B8 (io), B5 I/O10 B2 (io), B6 I/O7 A14 (io), B7 I/O5 A10 (io), B8 I/O0 A0 (io), C1 I/O39 C15 (io), C3 I/O22 B14 (io), C4 I/O23 B15 (io), C5 I/O14 B6 (io), C6 I/O12 B4 (io), C7 I/O6 A12 (io), D1 I/O37 C13 (io), D2 I/O38 C14 (io), D3 I/O17 B9 (io), E1 I/O31 C7 (io), E2 I/O35 C11 (io), E3 I/O36 C12 (io), E6 I/O8 B0 (io), E7 I/O2 A4 (io), F1 I/O29 C5 (io), F2 I/O30 C6 (io), F3 I/O32 C8 (io), F5 I/O34 C10 (io), F6 I/O11 B3 (io), F7 I/O4 A8 (io), G1 I/O47 D14 (io), G2 I/O25 C1 (io), G3 I/O26 C2 (io), G5 I/O28 C4 (io), G6 I/O33 C9 (io), H1 I/O42 D4 (io), H2 I/O43 D6 (io), H3 I/O44 D8 (io), H5 I/O24 C0 (io), H6 I/O27 C3 (io), J1 I/O50 E4 (io), J2 I/O48 E0 (io), J3 I/O49 E2 (io), J5 I/O45 D10 (io), J6 I/O46 D12 (io), K1 I/O56 F0 (io), K2 I/O54 E12 (io), K3 I/O55 E14 (io), K5 I/O40 D0 (io), K6 I/O41 D2 (io), L1 I/O57 F1 (io), L2 I/O60 F4 (io), L3 I/O59 F3 (io), L5 I/O51 E6 (io), L6 I/O52 E8 (io), L7 I/O77 G5 (io), L8 I/O75 G3 (io), L9 I/O91 H6 (io), M1 I/O58 F2 (io), M2 I/O63 F7 (io), M3 I/O68 F12 (io), M5 I/O53 E10 (io), M6 I/O83 G11 (io), M7 I/O80 G8 (io), M8 I/O74 G2 (io), M9 I/O90 H4 (io), N1 I/O61 F5 (io), N2 I/O64 F8 (io), P1 I/O62 F6 (io), P2 I/O65 F9 (io), P4 I/O87 G15 (io), P5 I/O84 G12 (io), P6 I/O79 G7 (io), P7 I/O94 H12 (io), P8 I/O93 H10 (io), P9 I/O89 H2 (io), R1 I/O66 F10 (io), R2 I/O67 F11 (io), R3 I/O71 F15 (io), R4 I/O85 G13 (io), R5 I/O81 G9 (io), R6 I/O76 G4 (io), R7 I/O72 G0 (io), R8 I/O92 H8 (io), T1 I/O69 F13 (io), T2 I/O70 F14 (io), T3 I/O86 G14 (io), T4 I/O82 G10 (io), T5 I/O78 G6 (io), T6 I/O73 G1 (io), T7 I/O95 H14 (io), T9 I/O88 H0 (io)
part B pins: A9 I/O186 P4 (io), A10 I/O191 P14 (io), A11 I/O172 O4 (io), A12 I/O174 O6 (io), A13 I/O177 O9 (io), A14 I/O180 O12 (io), A15 I/O181 O13 (io), A16 I/O167 N15 (io), B9 I/O187 P6 (io), B10 I/O168 O0 (io), B11 I/O173 O5 (io), B12 I/O175 O7 (io), B13 I/O179 O11 (io), B14 I/O182 O14 (io), B15 I/O166 N14 (io), B16 I/O165 N13 (io), C8 I/O184 P0 (io), C9 I/O189 P10 (io), C10 I/O171 O3 (io), C11 I/O170 O2 (io), C12 I/O178 O10 (io), C13 I/O183 O15 (io), C15 I/O164 N12 (io), C16 I/O163 N11 (io), D15 I/O159 N7 (io), D16 I/O158 N6 (io), E8 I/O188 P8 (io), E10 I/O190 P12 (io), E11 I/O161 N9 (io), E12 I/O160 N8 (io), E14 I/O162 N10 (io), E16 I/O156 N4 (io), F8 I/O185 P2 (io), F9 I/O169 O1 (io), F10 I/O176 O8 (io), F11 I/O153 N1 (io), F12 I/O154 N2 (io), F14 I/O155 N3 (io), F15 I/O157 N5 (io), F16 I/O152 N0 (io), G11 I/O151 M14 (io), G12 I/O148 M8 (io), G14 I/O149 M10 (io), G15 I/O150 M12 (io), G16 I/O147 M6 (io), H11 I/O137 L2 (io), H12 I/O136 L0 (io), H14 I/O145 M2 (io), H15 I/O146 M4 (io), H16 I/O144 M0 (io), J11 I/O141 L10 (io), J12 I/O142 L12 (io), J14 I/O140 L8 (io), J15 I/O139 L6 (io), J16 I/O138 L4 (io), K11 I/O122 K2 (io), K12 I/O123 K3 (io), K14 I/O121 K1 (io), K15 I/O120 K0 (io), K16 I/O143 L14 (io), L10 I/O98 I4 (io), L11 I/O126 K6 (io), L12 I/O130 K10 (io), L14 I/O127 K7 (io), L15 I/O125 K5 (io), L16 I/O124 K4 (io), M10 I/O100 I8 (io), M11 I/O105 J1 (io), M12 I/O107 J3 (io), M14 I/O131 K11 (io), M15 I/O129 K9 (io), M16 I/O128 K8 (io), N14 I/O135 K15 (io), N15 I/O133 K13 (io), N16 I/O132 K12 (io), P10 I/O101 I10 (io), P11 I/O106 J2 (io), P12 I/O108 J4 (io), P13 I/O119 J15 (io), P14 I/O118 J14 (io), P15 I/O117 J13 (io), P16 I/O134 K14 (io), R9 I/O96 I0 (io), R10 I/O99 I6 (io), R11 I/O102 I12 (io), R12 I/O104 J0 (io), R13 I/O111 J7 (io), R14 I/O112 J8 (io), R15 I/O115 J11 (io), R16 I/O116 J12 (io), T10 I/O97 I2 (io), T12 I/O103 I14 (io), T13 I/O109 J5 (io), T14 I/O110 J6 (io), T15 I/O113 J9 (io), T16 I/O114 J10 (io)
part C pins: A6 GCLK0 (in), B1 NC, C2 TDI (in), C14 NC, D4 VCC (power), D5 GND (power), D6 VCC (power), D7 GND (power), D8 GND (power), D9 VCC (power), D10 GND (power), D11 VCC (power), D12 GND (power), D13 GND (power), D14 TDO (out), E4 GND (power), E5 NC, E9 GCLK3 (in), E13 VCC (power), E15 NC, F4 VCC (power), F13 GND (power), G4 GND (power), G7 VCC (power), G8 GND (power), G9 GND (power), G10 VCC (power), G13 VCC (power), H4 VCC (power), H7 GND (power), H8 VCC (power), H9 VCC (power), H10 GND (power), H13 GND (power), J4 GND (power), J7 GND (power), J8 VCC (power), J9 VCC (power), J10 GND (power), J13 GND (power), K4 VCC (power), K7 VCC (power), K8 GND (power), K9 GND (power), K10 VCC (power), K13 VCC (power), L4 GND (power), L13 GND (power), M4 VCC (power), M13 GND (power), N3 TCK (in), N4 GND (power), N5 GND (power), N6 VCC (power), N7 GND (power), N8 GND (power), N9 VCC (power), N10 GND (power), N11 VCC (power), N12 GND (power), N13 VCC (power), P3 TMS (in), T8 GCLK1 (in), T11 GCLK2 (in)

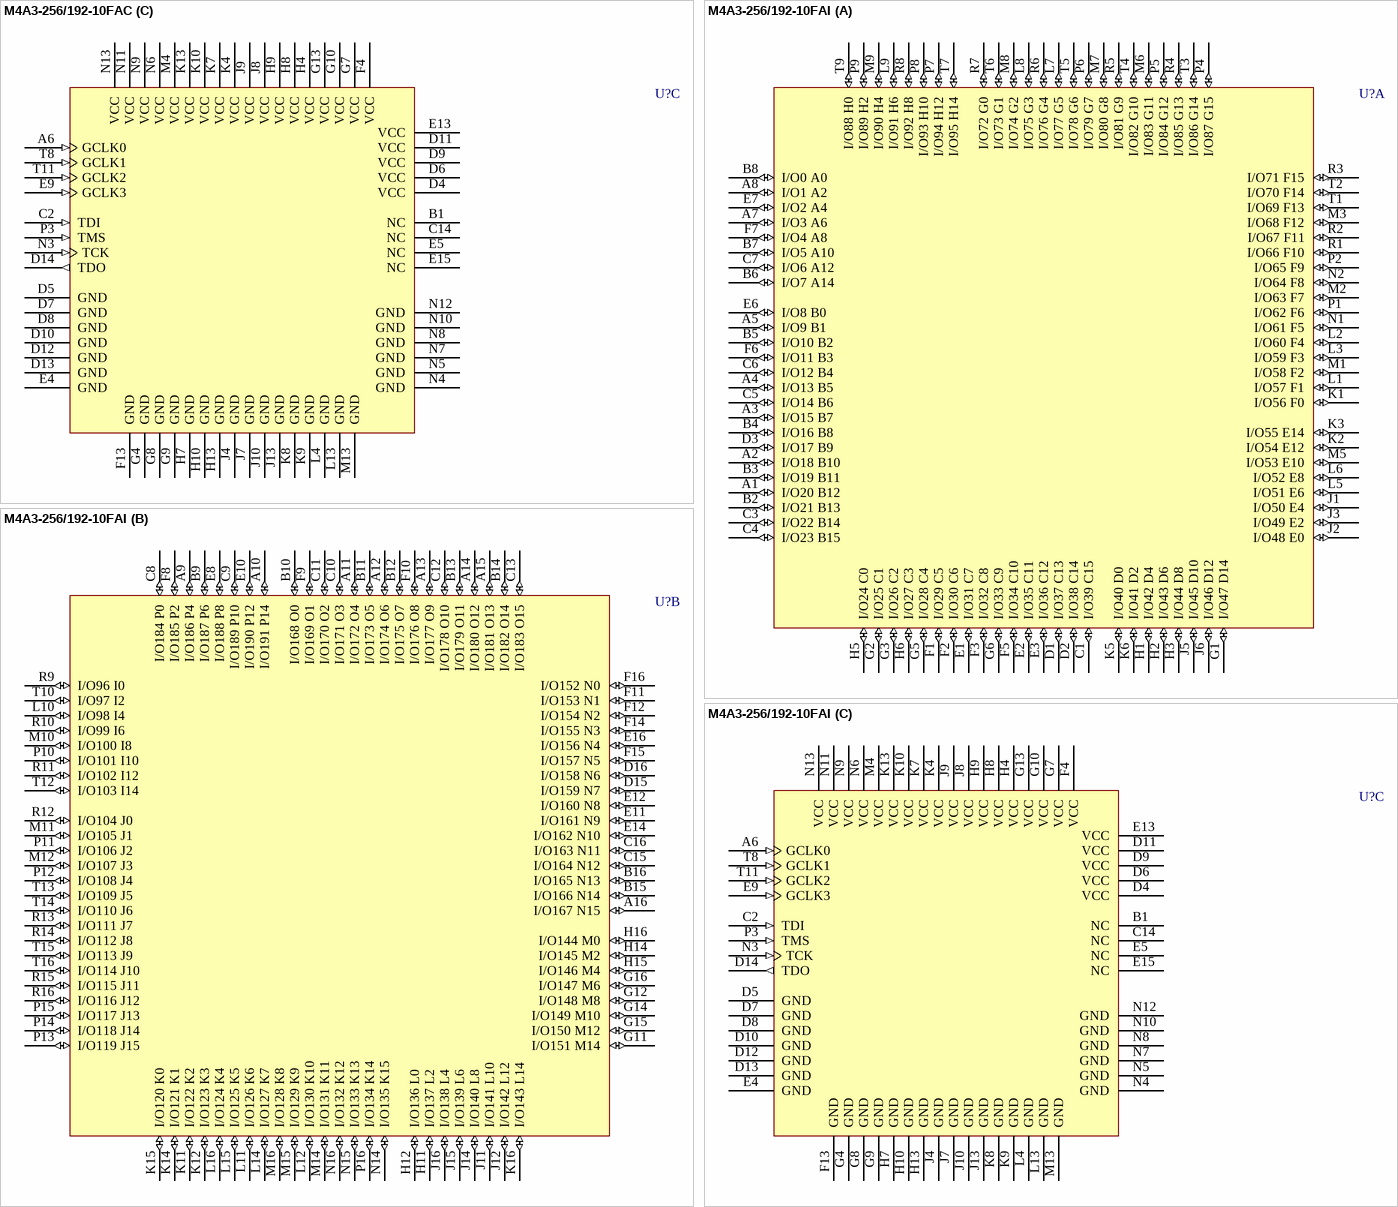
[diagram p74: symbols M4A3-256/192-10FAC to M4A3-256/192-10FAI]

## M4A3-256/192-10FAC
designator U?
High-Performance EE CMOS In-System Programmable Logic
footprint fpBGA256 (BGA, 256-Leads, Body 17x17mm, Pitch 1mm)
3D model M4A3-fpBGA256 (256-Ball Fine Pitch Ball Grid Array (fpBGA256))
part A pins: A1 I/O20 B12 (io), A2 I/O18 B10 (io), A3 I/O15 B7 (io), A4 I/O13 B5 (io), A5 I/O9 B1 (io), A7 I/O3 A6 (io), A8 I/O1 A2 (io), B2 I/O21 B13 (io), B3 I/O19 B11 (io), B4 I/O16 B8 (io), B5 I/O10 B2 (io), B6 I/O7 A14 (io), B7 I/O5 A10 (io), B8 I/O0 A0 (io), C1 I/O39 C15 (io), C3 I/O22 B14 (io), C4 I/O23 B15 (io), C5 I/O14 B6 (io), C6 I/O12 B4 (io), C7 I/O6 A12 (io), D1 I/O37 C13 (io), D2 I/O38 C14 (io), D3 I/O17 B9 (io), E1 I/O31 C7 (io), E2 I/O35 C11 (io), E3 I/O36 C12 (io), E6 I/O8 B0 (io), E7 I/O2 A4 (io), F1 I/O29 C5 (io), F2 I/O30 C6 (io), F3 I/O32 C8 (io), F5 I/O34 C10 (io), F6 I/O11 B3 (io), F7 I/O4 A8 (io), G1 I/O47 D14 (io), G2 I/O25 C1 (io), G3 I/O26 C2 (io), G5 I/O28 C4 (io), G6 I/O33 C9 (io), H1 I/O42 D4 (io), H2 I/O43 D6 (io), H3 I/O44 D8 (io), H5 I/O24 C0 (io), H6 I/O27 C3 (io), J1 I/O50 E4 (io), J2 I/O48 E0 (io), J3 I/O49 E2 (io), J5 I/O45 D10 (io), J6 I/O46 D12 (io), K1 I/O56 F0 (io), K2 I/O54 E12 (io), K3 I/O55 E14 (io), K5 I/O40 D0 (io), K6 I/O41 D2 (io), L1 I/O57 F1 (io), L2 I/O60 F4 (io), L3 I/O59 F3 (io), L5 I/O51 E6 (io), L6 I/O52 E8 (io), L7 I/O77 G5 (io), L8 I/O75 G3 (io), L9 I/O91 H6 (io), M1 I/O58 F2 (io), M2 I/O63 F7 (io), M3 I/O68 F12 (io), M5 I/O53 E10 (io), M6 I/O83 G11 (io), M7 I/O80 G8 (io), M8 I/O74 G2 (io), M9 I/O90 H4 (io), N1 I/O61 F5 (io), N2 I/O64 F8 (io), P1 I/O62 F6 (io), P2 I/O65 F9 (io), P4 I/O87 G15 (io), P5 I/O84 G12 (io), P6 I/O79 G7 (io), P7 I/O94 H12 (io), P8 I/O93 H10 (io), P9 I/O89 H2 (io), R1 I/O66 F10 (io), R2 I/O67 F11 (io), R3 I/O71 F15 (io), R4 I/O85 G13 (io), R5 I/O81 G9 (io), R6 I/O76 G4 (io), R7 I/O72 G0 (io), R8 I/O92 H8 (io), T1 I/O69 F13 (io), T2 I/O70 F14 (io), T3 I/O86 G14 (io), T4 I/O82 G10 (io), T5 I/O78 G6 (io), T6 I/O73 G1 (io), T7 I/O95 H14 (io), T9 I/O88 H0 (io)
part B pins: A9 I/O186 P4 (io), A10 I/O191 P14 (io), A11 I/O172 O4 (io), A12 I/O174 O6 (io), A13 I/O177 O9 (io), A14 I/O180 O12 (io), A15 I/O181 O13 (io), A16 I/O167 N15 (io), B9 I/O187 P6 (io), B10 I/O168 O0 (io), B11 I/O173 O5 (io), B12 I/O175 O7 (io), B13 I/O179 O11 (io), B14 I/O182 O14 (io), B15 I/O166 N14 (io), B16 I/O165 N13 (io), C8 I/O184 P0 (io), C9 I/O189 P10 (io), C10 I/O171 O3 (io), C11 I/O170 O2 (io), C12 I/O178 O10 (io), C13 I/O183 O15 (io), C15 I/O164 N12 (io), C16 I/O163 N11 (io), D15 I/O159 N7 (io), D16 I/O158 N6 (io), E8 I/O188 P8 (io), E10 I/O190 P12 (io), E11 I/O161 N9 (io), E12 I/O160 N8 (io), E14 I/O162 N10 (io), E16 I/O156 N4 (io), F8 I/O185 P2 (io), F9 I/O169 O1 (io), F10 I/O176 O8 (io), F11 I/O153 N1 (io), F12 I/O154 N2 (io), F14 I/O155 N3 (io), F15 I/O157 N5 (io), F16 I/O152 N0 (io), G11 I/O151 M14 (io), G12 I/O148 M8 (io), G14 I/O149 M10 (io), G15 I/O150 M12 (io), G16 I/O147 M6 (io), H11 I/O137 L2 (io), H12 I/O136 L0 (io), H14 I/O145 M2 (io), H15 I/O146 M4 (io), H16 I/O144 M0 (io), J11 I/O141 L10 (io), J12 I/O142 L12 (io), J14 I/O140 L8 (io), J15 I/O139 L6 (io), J16 I/O138 L4 (io), K11 I/O122 K2 (io), K12 I/O123 K3 (io), K14 I/O121 K1 (io), K15 I/O120 K0 (io), K16 I/O143 L14 (io), L10 I/O98 I4 (io), L11 I/O126 K6 (io), L12 I/O130 K10 (io), L14 I/O127 K7 (io), L15 I/O125 K5 (io), L16 I/O124 K4 (io), M10 I/O100 I8 (io), M11 I/O105 J1 (io), M12 I/O107 J3 (io), M14 I/O131 K11 (io), M15 I/O129 K9 (io), M16 I/O128 K8 (io), N14 I/O135 K15 (io), N15 I/O133 K13 (io), N16 I/O132 K12 (io), P10 I/O101 I10 (io), P11 I/O106 J2 (io), P12 I/O108 J4 (io), P13 I/O119 J15 (io), P14 I/O118 J14 (io), P15 I/O117 J13 (io), P16 I/O134 K14 (io), R9 I/O96 I0 (io), R10 I/O99 I6 (io), R11 I/O102 I12 (io), R12 I/O104 J0 (io), R13 I/O111 J7 (io), R14 I/O112 J8 (io), R15 I/O115 J11 (io), R16 I/O116 J12 (io), T10 I/O97 I2 (io), T12 I/O103 I14 (io), T13 I/O109 J5 (io), T14 I/O110 J6 (io), T15 I/O113 J9 (io), T16 I/O114 J10 (io)
part C pins: A6 GCLK0 (in), B1 NC, C2 TDI (in), C14 NC, D4 VCC (power), D5 GND (power), D6 VCC (power), D7 GND (power), D8 GND (power), D9 VCC (power), D10 GND (power), D11 VCC (power), D12 GND (power), D13 GND (power), D14 TDO (out), E4 GND (power), E5 NC, E9 GCLK3 (in), E13 VCC (power), E15 NC, F4 VCC (power), F13 GND (power), G4 GND (power), G7 VCC (power), G8 GND (power), G9 GND (power), G10 VCC (power), G13 VCC (power), H4 VCC (power), H7 GND (power), H8 VCC (power), H9 VCC (power), H10 GND (power), H13 GND (power), J4 GND (power), J7 GND (power), J8 VCC (power), J9 VCC (power), J10 GND (power), J13 GND (power), K4 VCC (power), K7 VCC (power), K8 GND (power), K9 GND (power), K10 VCC (power), K13 VCC (power), L4 GND (power), L13 GND (power), M4 VCC (power), M13 GND (power), N3 TCK (in), N4 GND (power), N5 GND (power), N6 VCC (power), N7 GND (power), N8 GND (power), N9 VCC (power), N10 GND (power), N11 VCC (power), N12 GND (power), N13 VCC (power), P3 TMS (in), T8 GCLK1 (in), T11 GCLK2 (in)

## M4A3-256/192-10FAI
designator U?
High-Performance EE CMOS In-System Programmable Logic
footprint fpBGA256 (BGA, 256-Leads, Body 17x17mm, Pitch 1mm)
3D model M4A3-fpBGA256 (256-Ball Fine Pitch Ball Grid Array (fpBGA256))
part A pins: A1 I/O20 B12 (io), A2 I/O18 B10 (io), A3 I/O15 B7 (io), A4 I/O13 B5 (io), A5 I/O9 B1 (io), A7 I/O3 A6 (io), A8 I/O1 A2 (io), B2 I/O21 B13 (io), B3 I/O19 B11 (io), B4 I/O16 B8 (io), B5 I/O10 B2 (io), B6 I/O7 A14 (io), B7 I/O5 A10 (io), B8 I/O0 A0 (io), C1 I/O39 C15 (io), C3 I/O22 B14 (io), C4 I/O23 B15 (io), C5 I/O14 B6 (io), C6 I/O12 B4 (io), C7 I/O6 A12 (io), D1 I/O37 C13 (io), D2 I/O38 C14 (io), D3 I/O17 B9 (io), E1 I/O31 C7 (io), E2 I/O35 C11 (io), E3 I/O36 C12 (io), E6 I/O8 B0 (io), E7 I/O2 A4 (io), F1 I/O29 C5 (io), F2 I/O30 C6 (io), F3 I/O32 C8 (io), F5 I/O34 C10 (io), F6 I/O11 B3 (io), F7 I/O4 A8 (io), G1 I/O47 D14 (io), G2 I/O25 C1 (io), G3 I/O26 C2 (io), G5 I/O28 C4 (io), G6 I/O33 C9 (io), H1 I/O42 D4 (io), H2 I/O43 D6 (io), H3 I/O44 D8 (io), H5 I/O24 C0 (io), H6 I/O27 C3 (io), J1 I/O50 E4 (io), J2 I/O48 E0 (io), J3 I/O49 E2 (io), J5 I/O45 D10 (io), J6 I/O46 D12 (io), K1 I/O56 F0 (io), K2 I/O54 E12 (io), K3 I/O55 E14 (io), K5 I/O40 D0 (io), K6 I/O41 D2 (io), L1 I/O57 F1 (io), L2 I/O60 F4 (io), L3 I/O59 F3 (io), L5 I/O51 E6 (io), L6 I/O52 E8 (io), L7 I/O77 G5 (io), L8 I/O75 G3 (io), L9 I/O91 H6 (io), M1 I/O58 F2 (io), M2 I/O63 F7 (io), M3 I/O68 F12 (io), M5 I/O53 E10 (io), M6 I/O83 G11 (io), M7 I/O80 G8 (io), M8 I/O74 G2 (io), M9 I/O90 H4 (io), N1 I/O61 F5 (io), N2 I/O64 F8 (io), P1 I/O62 F6 (io), P2 I/O65 F9 (io), P4 I/O87 G15 (io), P5 I/O84 G12 (io), P6 I/O79 G7 (io), P7 I/O94 H12 (io), P8 I/O93 H10 (io), P9 I/O89 H2 (io), R1 I/O66 F10 (io), R2 I/O67 F11 (io), R3 I/O71 F15 (io), R4 I/O85 G13 (io), R5 I/O81 G9 (io), R6 I/O76 G4 (io), R7 I/O72 G0 (io), R8 I/O92 H8 (io), T1 I/O69 F13 (io), T2 I/O70 F14 (io), T3 I/O86 G14 (io), T4 I/O82 G10 (io), T5 I/O78 G6 (io), T6 I/O73 G1 (io), T7 I/O95 H14 (io), T9 I/O88 H0 (io)
part B pins: A9 I/O186 P4 (io), A10 I/O191 P14 (io), A11 I/O172 O4 (io), A12 I/O174 O6 (io), A13 I/O177 O9 (io), A14 I/O180 O12 (io), A15 I/O181 O13 (io), A16 I/O167 N15 (io), B9 I/O187 P6 (io), B10 I/O168 O0 (io), B11 I/O173 O5 (io), B12 I/O175 O7 (io), B13 I/O179 O11 (io), B14 I/O182 O14 (io), B15 I/O166 N14 (io), B16 I/O165 N13 (io), C8 I/O184 P0 (io), C9 I/O189 P10 (io), C10 I/O171 O3 (io), C11 I/O170 O2 (io), C12 I/O178 O10 (io), C13 I/O183 O15 (io), C15 I/O164 N12 (io), C16 I/O163 N11 (io), D15 I/O159 N7 (io), D16 I/O158 N6 (io), E8 I/O188 P8 (io), E10 I/O190 P12 (io), E11 I/O161 N9 (io), E12 I/O160 N8 (io), E14 I/O162 N10 (io), E16 I/O156 N4 (io), F8 I/O185 P2 (io), F9 I/O169 O1 (io), F10 I/O176 O8 (io), F11 I/O153 N1 (io), F12 I/O154 N2 (io), F14 I/O155 N3 (io), F15 I/O157 N5 (io), F16 I/O152 N0 (io), G11 I/O151 M14 (io), G12 I/O148 M8 (io), G14 I/O149 M10 (io), G15 I/O150 M12 (io), G16 I/O147 M6 (io), H11 I/O137 L2 (io), H12 I/O136 L0 (io), H14 I/O145 M2 (io), H15 I/O146 M4 (io), H16 I/O144 M0 (io), J11 I/O141 L10 (io), J12 I/O142 L12 (io), J14 I/O140 L8 (io), J15 I/O139 L6 (io), J16 I/O138 L4 (io), K11 I/O122 K2 (io), K12 I/O123 K3 (io), K14 I/O121 K1 (io), K15 I/O120 K0 (io), K16 I/O143 L14 (io), L10 I/O98 I4 (io), L11 I/O126 K6 (io), L12 I/O130 K10 (io), L14 I/O127 K7 (io), L15 I/O125 K5 (io), L16 I/O124 K4 (io), M10 I/O100 I8 (io), M11 I/O105 J1 (io), M12 I/O107 J3 (io), M14 I/O131 K11 (io), M15 I/O129 K9 (io), M16 I/O128 K8 (io), N14 I/O135 K15 (io), N15 I/O133 K13 (io), N16 I/O132 K12 (io), P10 I/O101 I10 (io), P11 I/O106 J2 (io), P12 I/O108 J4 (io), P13 I/O119 J15 (io), P14 I/O118 J14 (io), P15 I/O117 J13 (io), P16 I/O134 K14 (io), R9 I/O96 I0 (io), R10 I/O99 I6 (io), R11 I/O102 I12 (io), R12 I/O104 J0 (io), R13 I/O111 J7 (io), R14 I/O112 J8 (io), R15 I/O115 J11 (io), R16 I/O116 J12 (io), T10 I/O97 I2 (io), T12 I/O103 I14 (io), T13 I/O109 J5 (io), T14 I/O110 J6 (io), T15 I/O113 J9 (io), T16 I/O114 J10 (io)
part C pins: A6 GCLK0 (in), B1 NC, C2 TDI (in), C14 NC, D4 VCC (power), D5 GND (power), D6 VCC (power), D7 GND (power), D8 GND (power), D9 VCC (power), D10 GND (power), D11 VCC (power), D12 GND (power), D13 GND (power), D14 TDO (out), E4 GND (power), E5 NC, E9 GCLK3 (in), E13 VCC (power), E15 NC, F4 VCC (power), F13 GND (power), G4 GND (power), G7 VCC (power), G8 GND (power), G9 GND (power), G10 VCC (power), G13 VCC (power), H4 VCC (power), H7 GND (power), H8 VCC (power), H9 VCC (power), H10 GND (power), H13 GND (power), J4 GND (power), J7 GND (power), J8 VCC (power), J9 VCC (power), J10 GND (power), J13 GND (power), K4 VCC (power), K7 VCC (power), K8 GND (power), K9 GND (power), K10 VCC (power), K13 VCC (power), L4 GND (power), L13 GND (power), M4 VCC (power), M13 GND (power), N3 TCK (in), N4 GND (power), N5 GND (power), N6 VCC (power), N7 GND (power), N8 GND (power), N9 VCC (power), N10 GND (power), N11 VCC (power), N12 GND (power), N13 VCC (power), P3 TMS (in), T8 GCLK1 (in), T11 GCLK2 (in)

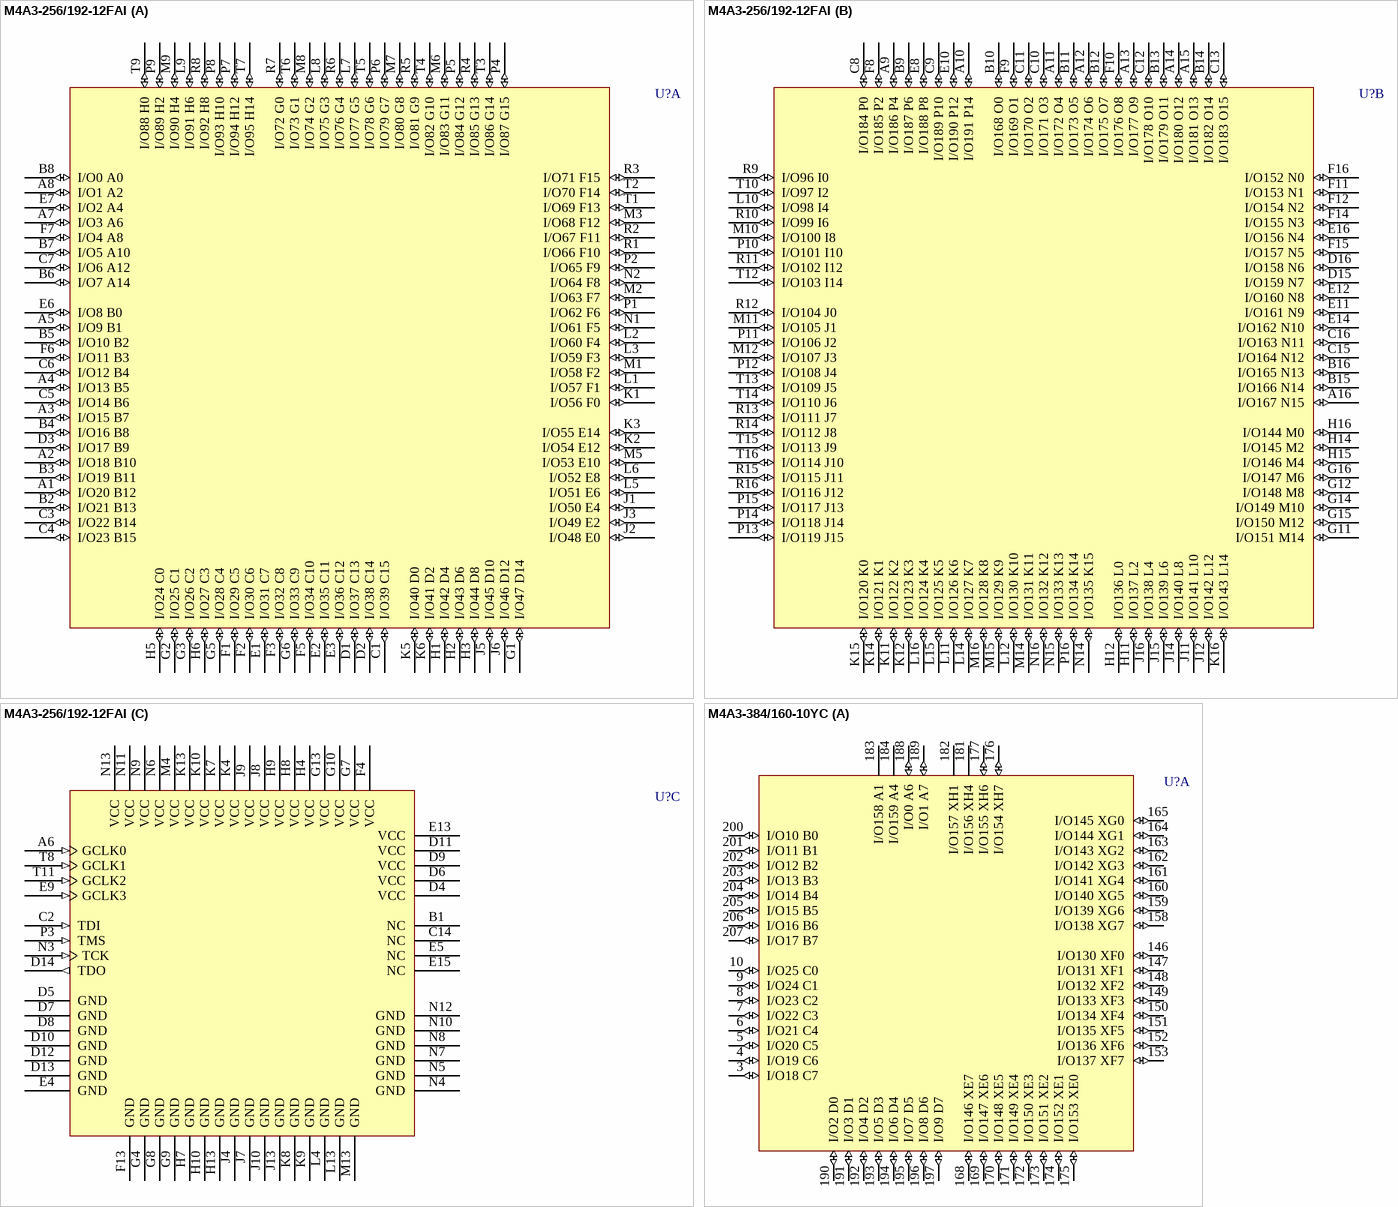
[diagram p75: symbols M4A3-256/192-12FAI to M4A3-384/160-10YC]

## M4A3-256/192-12FAI
designator U?
High-Performance EE CMOS In-System Programmable Logic
footprint fpBGA256 (BGA, 256-Leads, Body 17x17mm, Pitch 1mm)
3D model M4A3-fpBGA256 (256-Ball Fine Pitch Ball Grid Array (fpBGA256))
part A pins: A1 I/O20 B12 (io), A2 I/O18 B10 (io), A3 I/O15 B7 (io), A4 I/O13 B5 (io), A5 I/O9 B1 (io), A7 I/O3 A6 (io), A8 I/O1 A2 (io), B2 I/O21 B13 (io), B3 I/O19 B11 (io), B4 I/O16 B8 (io), B5 I/O10 B2 (io), B6 I/O7 A14 (io), B7 I/O5 A10 (io), B8 I/O0 A0 (io), C1 I/O39 C15 (io), C3 I/O22 B14 (io), C4 I/O23 B15 (io), C5 I/O14 B6 (io), C6 I/O12 B4 (io), C7 I/O6 A12 (io), D1 I/O37 C13 (io), D2 I/O38 C14 (io), D3 I/O17 B9 (io), E1 I/O31 C7 (io), E2 I/O35 C11 (io), E3 I/O36 C12 (io), E6 I/O8 B0 (io), E7 I/O2 A4 (io), F1 I/O29 C5 (io), F2 I/O30 C6 (io), F3 I/O32 C8 (io), F5 I/O34 C10 (io), F6 I/O11 B3 (io), F7 I/O4 A8 (io), G1 I/O47 D14 (io), G2 I/O25 C1 (io), G3 I/O26 C2 (io), G5 I/O28 C4 (io), G6 I/O33 C9 (io), H1 I/O42 D4 (io), H2 I/O43 D6 (io), H3 I/O44 D8 (io), H5 I/O24 C0 (io), H6 I/O27 C3 (io), J1 I/O50 E4 (io), J2 I/O48 E0 (io), J3 I/O49 E2 (io), J5 I/O45 D10 (io), J6 I/O46 D12 (io), K1 I/O56 F0 (io), K2 I/O54 E12 (io), K3 I/O55 E14 (io), K5 I/O40 D0 (io), K6 I/O41 D2 (io), L1 I/O57 F1 (io), L2 I/O60 F4 (io), L3 I/O59 F3 (io), L5 I/O51 E6 (io), L6 I/O52 E8 (io), L7 I/O77 G5 (io), L8 I/O75 G3 (io), L9 I/O91 H6 (io), M1 I/O58 F2 (io), M2 I/O63 F7 (io), M3 I/O68 F12 (io), M5 I/O53 E10 (io), M6 I/O83 G11 (io), M7 I/O80 G8 (io), M8 I/O74 G2 (io), M9 I/O90 H4 (io), N1 I/O61 F5 (io), N2 I/O64 F8 (io), P1 I/O62 F6 (io), P2 I/O65 F9 (io), P4 I/O87 G15 (io), P5 I/O84 G12 (io), P6 I/O79 G7 (io), P7 I/O94 H12 (io), P8 I/O93 H10 (io), P9 I/O89 H2 (io), R1 I/O66 F10 (io), R2 I/O67 F11 (io), R3 I/O71 F15 (io), R4 I/O85 G13 (io), R5 I/O81 G9 (io), R6 I/O76 G4 (io), R7 I/O72 G0 (io), R8 I/O92 H8 (io), T1 I/O69 F13 (io), T2 I/O70 F14 (io), T3 I/O86 G14 (io), T4 I/O82 G10 (io), T5 I/O78 G6 (io), T6 I/O73 G1 (io), T7 I/O95 H14 (io), T9 I/O88 H0 (io)
part B pins: A9 I/O186 P4 (io), A10 I/O191 P14 (io), A11 I/O172 O4 (io), A12 I/O174 O6 (io), A13 I/O177 O9 (io), A14 I/O180 O12 (io), A15 I/O181 O13 (io), A16 I/O167 N15 (io), B9 I/O187 P6 (io), B10 I/O168 O0 (io), B11 I/O173 O5 (io), B12 I/O175 O7 (io), B13 I/O179 O11 (io), B14 I/O182 O14 (io), B15 I/O166 N14 (io), B16 I/O165 N13 (io), C8 I/O184 P0 (io), C9 I/O189 P10 (io), C10 I/O171 O3 (io), C11 I/O170 O2 (io), C12 I/O178 O10 (io), C13 I/O183 O15 (io), C15 I/O164 N12 (io), C16 I/O163 N11 (io), D15 I/O159 N7 (io), D16 I/O158 N6 (io), E8 I/O188 P8 (io), E10 I/O190 P12 (io), E11 I/O161 N9 (io), E12 I/O160 N8 (io), E14 I/O162 N10 (io), E16 I/O156 N4 (io), F8 I/O185 P2 (io), F9 I/O169 O1 (io), F10 I/O176 O8 (io), F11 I/O153 N1 (io), F12 I/O154 N2 (io), F14 I/O155 N3 (io), F15 I/O157 N5 (io), F16 I/O152 N0 (io), G11 I/O151 M14 (io), G12 I/O148 M8 (io), G14 I/O149 M10 (io), G15 I/O150 M12 (io), G16 I/O147 M6 (io), H11 I/O137 L2 (io), H12 I/O136 L0 (io), H14 I/O145 M2 (io), H15 I/O146 M4 (io), H16 I/O144 M0 (io), J11 I/O141 L10 (io), J12 I/O142 L12 (io), J14 I/O140 L8 (io), J15 I/O139 L6 (io), J16 I/O138 L4 (io), K11 I/O122 K2 (io), K12 I/O123 K3 (io), K14 I/O121 K1 (io), K15 I/O120 K0 (io), K16 I/O143 L14 (io), L10 I/O98 I4 (io), L11 I/O126 K6 (io), L12 I/O130 K10 (io), L14 I/O127 K7 (io), L15 I/O125 K5 (io), L16 I/O124 K4 (io), M10 I/O100 I8 (io), M11 I/O105 J1 (io), M12 I/O107 J3 (io), M14 I/O131 K11 (io), M15 I/O129 K9 (io), M16 I/O128 K8 (io), N14 I/O135 K15 (io), N15 I/O133 K13 (io), N16 I/O132 K12 (io), P10 I/O101 I10 (io), P11 I/O106 J2 (io), P12 I/O108 J4 (io), P13 I/O119 J15 (io), P14 I/O118 J14 (io), P15 I/O117 J13 (io), P16 I/O134 K14 (io), R9 I/O96 I0 (io), R10 I/O99 I6 (io), R11 I/O102 I12 (io), R12 I/O104 J0 (io), R13 I/O111 J7 (io), R14 I/O112 J8 (io), R15 I/O115 J11 (io), R16 I/O116 J12 (io), T10 I/O97 I2 (io), T12 I/O103 I14 (io), T13 I/O109 J5 (io), T14 I/O110 J6 (io), T15 I/O113 J9 (io), T16 I/O114 J10 (io)
part C pins: A6 GCLK0 (in), B1 NC, C2 TDI (in), C14 NC, D4 VCC (power), D5 GND (power), D6 VCC (power), D7 GND (power), D8 GND (power), D9 VCC (power), D10 GND (power), D11 VCC (power), D12 GND (power), D13 GND (power), D14 TDO (out), E4 GND (power), E5 NC, E9 GCLK3 (in), E13 VCC (power), E15 NC, F4 VCC (power), F13 GND (power), G4 GND (power), G7 VCC (power), G8 GND (power), G9 GND (power), G10 VCC (power), G13 VCC (power), H4 VCC (power), H7 GND (power), H8 VCC (power), H9 VCC (power), H10 GND (power), H13 GND (power), J4 GND (power), J7 GND (power), J8 VCC (power), J9 VCC (power), J10 GND (power), J13 GND (power), K4 VCC (power), K7 VCC (power), K8 GND (power), K9 GND (power), K10 VCC (power), K13 VCC (power), L4 GND (power), L13 GND (power), M4 VCC (power), M13 GND (power), N3 TCK (in), N4 GND (power), N5 GND (power), N6 VCC (power), N7 GND (power), N8 GND (power), N9 VCC (power), N10 GND (power), N11 VCC (power), N12 GND (power), N13 VCC (power), P3 TMS (in), T8 GCLK1 (in), T11 GCLK2 (in)

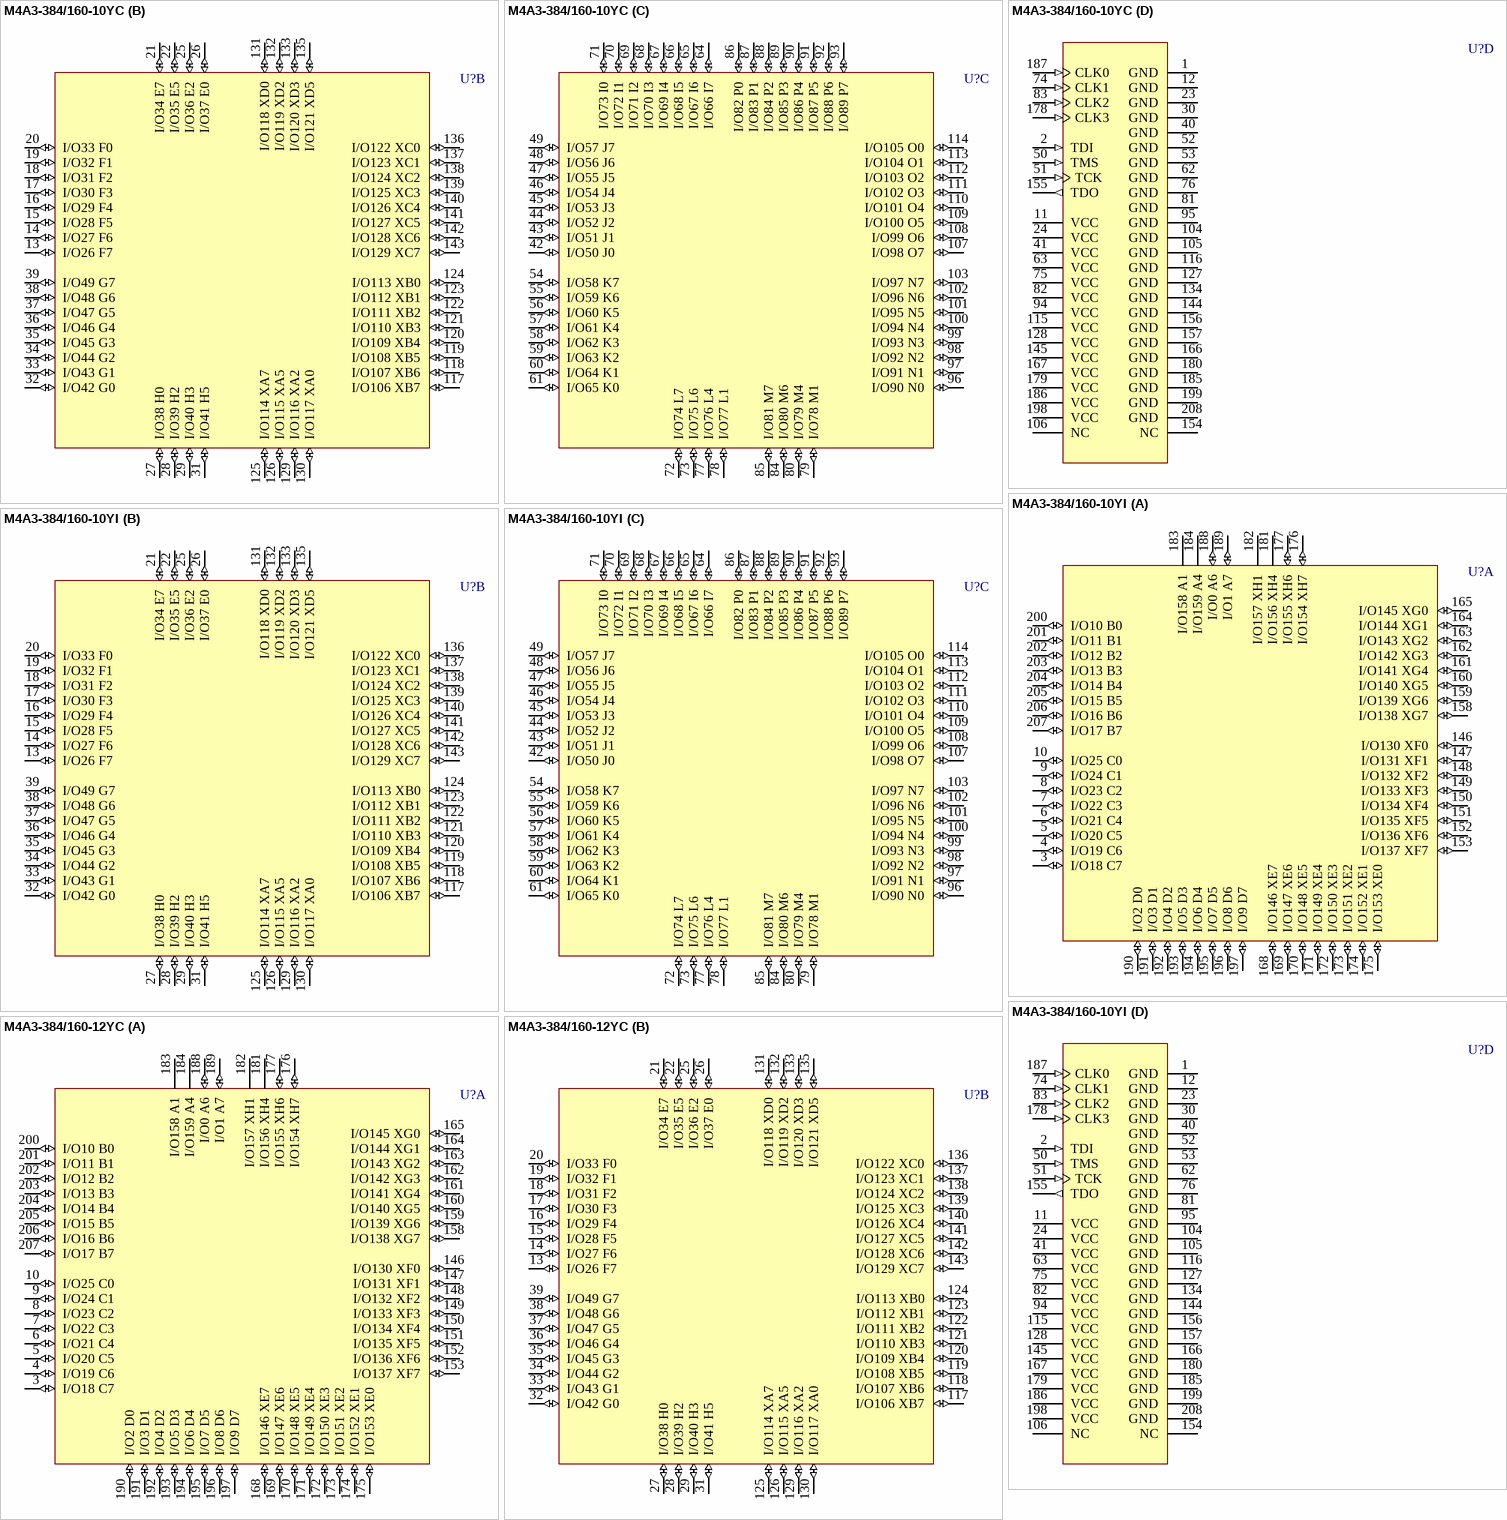
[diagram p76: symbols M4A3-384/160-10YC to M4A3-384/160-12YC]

## M4A3-384/160-10YC
designator U?
High-Performance EE CMOS In-System Programmable Logic
footprint PQFP208_N (Shrink QFP, 208-Leads, Body 28x28mm, Pitch 0.5mm, IPC Medium Density)
footprint PQFP208_L (Shrink QFP, 208-Leads, Body 28x28mm, Pitch 0.5mm, IPC High Density)
footprint PQFP208_M (Shrink QFP, 208-Leads, Body 28x28mm, Pitch 0.5mm, IPC Low Density)
3D model M4A3-PQFP208 (208-Pin Plastic Quad Flat Pack (PQFP208))
part A pins: 3 I/O18 C7 (io), 4 I/O19 C6 (io), 5 I/O20 C5 (io), 6 I/O21 C4 (io), 7 I/O22 C3 (io), 8 I/O23 C2 (io), 9 I/O24 C1 (io), 10 I/O25 C0 (io), 146 I/O130 XF0 (io), 147 I/O131 XF1 (io), 148 I/O132 XF2 (io), 149 I/O133 XF3 (io), 150 I/O134 XF4 (io), 151 I/O135 XF5 (io), 152 I/O136 XF6 (io), 153 I/O137 XF7 (io), 158 I/O138 XG7 (io), 159 I/O139 XG6 (io), 160 I/O140 XG5 (io), 161 I/O141 XG4 (io), 162 I/O142 XG3 (io), 163 I/O143 XG2 (io), 164 I/O144 XG1 (io), 165 I/O145 XG0 (io), 168 I/O146 XE7 (io), 169 I/O147 XE6 (io), 170 I/O148 XE5 (io), 171 I/O149 XE4 (io), 172 I/O150 XE3 (io), 173 I/O151 XE2 (io), 174 I/O152 XE1 (io), 175 I/O153 XE0 (io), 176 I/O154 XH7 (io), 177 I/O155 XH6 (io), 181 I/O156 XH4 (power), 182 I/O157 XH1 (power), 183 I/O158 A1 (power), 184 I/O159 A4 (power), 188 I/O0 A6 (io), 189 I/O1 A7 (io), 190 I/O2 D0 (io), 191 I/O3 D1 (io), 192 I/O4 D2 (io), 193 I/O5 D3 (io), 194 I/O6 D4 (io), 195 I/O7 D5 (io), 196 I/O8 D6 (io), 197 I/O9 D7 (io), 200 I/O10 B0 (io), 201 I/O11 B1 (io), 202 I/O12 B2 (io), 203 I/O13 B3 (io), 204 I/O14 B4 (io), 205 I/O15 B5 (io), 206 I/O16 B6 (io), 207 I/O17 B7 (io)
part B pins: 13 I/O26 F7 (io), 14 I/O27 F6 (io), 15 I/O28 F5 (io), 16 I/O29 F4 (io), 17 I/O30 F3 (io), 18 I/O31 F2 (io), 19 I/O32 F1 (io), 20 I/O33 F0 (io), 21 I/O34 E7 (io), 22 I/O35 E5 (io), 25 I/O36 E2 (io), 26 I/O37 E0 (io), 27 I/O38 H0 (io), 28 I/O39 H2 (io), 29 I/O40 H3 (io), 31 I/O41 H5 (io), 32 I/O42 G0 (io), 33 I/O43 G1 (io), 34 I/O44 G2 (io), 35 I/O45 G3 (io), 36 I/O46 G4 (io), 37 I/O47 G5 (io), 38 I/O48 G6 (io), 39 I/O49 G7 (io), 117 I/O106 XB7 (io), 118 I/O107 XB6 (io), 119 I/O108 XB5 (io), 120 I/O109 XB4 (io), 121 I/O110 XB3 (io), 122 I/O111 XB2 (io), 123 I/O112 XB1 (io), 124 I/O113 XB0 (io), 125 I/O114 XA7 (io), 126 I/O115 XA5 (io), 129 I/O116 XA2 (io), 130 I/O117 XA0 (io), 131 I/O118 XD0 (io), 132 I/O119 XD2 (io), 133 I/O120 XD3 (io), 135 I/O121 XD5 (io), 136 I/O122 XC0 (io), 137 I/O123 XC1 (io), 138 I/O124 XC2 (io), 139 I/O125 XC3 (io), 140 I/O126 XC4 (io), 141 I/O127 XC5 (io), 142 I/O128 XC6 (io), 143 I/O129 XC7 (io)
part C pins: 42 I/O50 J0 (io), 43 I/O51 J1 (io), 44 I/O52 J2 (io), 45 I/O53 J3 (io), 46 I/O54 J4 (io), 47 I/O55 J5 (io), 48 I/O56 J6 (io), 49 I/O57 J7 (io), 54 I/O58 K7 (io), 55 I/O59 K6 (io), 56 I/O60 K5 (io), 57 I/O61 K4 (io), 58 I/O62 K3 (io), 59 I/O63 K2 (io), 60 I/O64 K1 (io), 61 I/O65 K0 (io), 64 I/O66 I7 (io), 65 I/O67 I6 (io), 66 I/O68 I5 (io), 67 I/O69 I4 (io), 68 I/O70 I3 (io), 69 I/O71 I2 (io), 70 I/O72 I1 (io), 71 I/O73 I0 (io), 72 I/O74 L7 (io), 73 I/O75 L6 (io), 77 I/O76 L4 (io), 78 I/O77 L1 (io), 79 I/O78 M1 (io), 80 I/O79 M4 (io), 84 I/O80 M6 (io), 85 I/O81 M7 (io), 86 I/O82 P0 (io), 87 I/O83 P1 (io), 88 I/O84 P2 (io), 89 I/O85 P3 (io), 90 I/O86 P4 (io), 91 I/O87 P5 (io), 92 I/O88 P6 (io), 93 I/O89 P7 (io), 96 I/O90 N0 (io), 97 I/O91 N1 (io), 98 I/O92 N2 (io), 99 I/O93 N3 (io), 100 I/O94 N4 (io), 101 I/O95 N5 (io), 102 I/O96 N6 (io), 103 I/O97 N7 (io), 107 I/O98 O7 (io), 108 I/O99 O6 (io), 109 I/O100 O5 (io), 110 I/O101 O4 (io), 111 I/O102 O3 (io), 112 I/O103 O2 (io), 113 I/O104 O1 (io), 114 I/O105 O0 (io)
part D pins: 1 GND (power), 2 TDI (in), 11 VCC (power), 12 GND (power), 23 GND (power), 24 VCC (power), 30 GND (power), 40 GND (power), 41 VCC (power), 50 TMS (in), 51 TCK (in), 52 GND (power), 53 GND (power), 62 GND (power), 63 VCC (power), 74 CLK1 (in), 75 VCC (power), 76 GND (power), 81 GND (power), 82 VCC (power), 83 CLK2 (in), 94 VCC (power), 95 GND (power), 104 GND (power), 105 GND (power), 106 NC, 115 VCC (power), 116 GND (power), 127 GND (power), 128 VCC (power), 134 GND (power), 144 GND (power), 145 VCC (power), 154 NC, 155 TDO (out), 156 GND (power), 157 GND (power), 166 GND (power), 167 VCC (power), 178 CLK3 (in), 179 VCC (power), 180 GND (power), 185 GND (power), 186 VCC (power), 187 CLK0 (in), 198 VCC (power), 199 GND (power), 208 GND (power)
